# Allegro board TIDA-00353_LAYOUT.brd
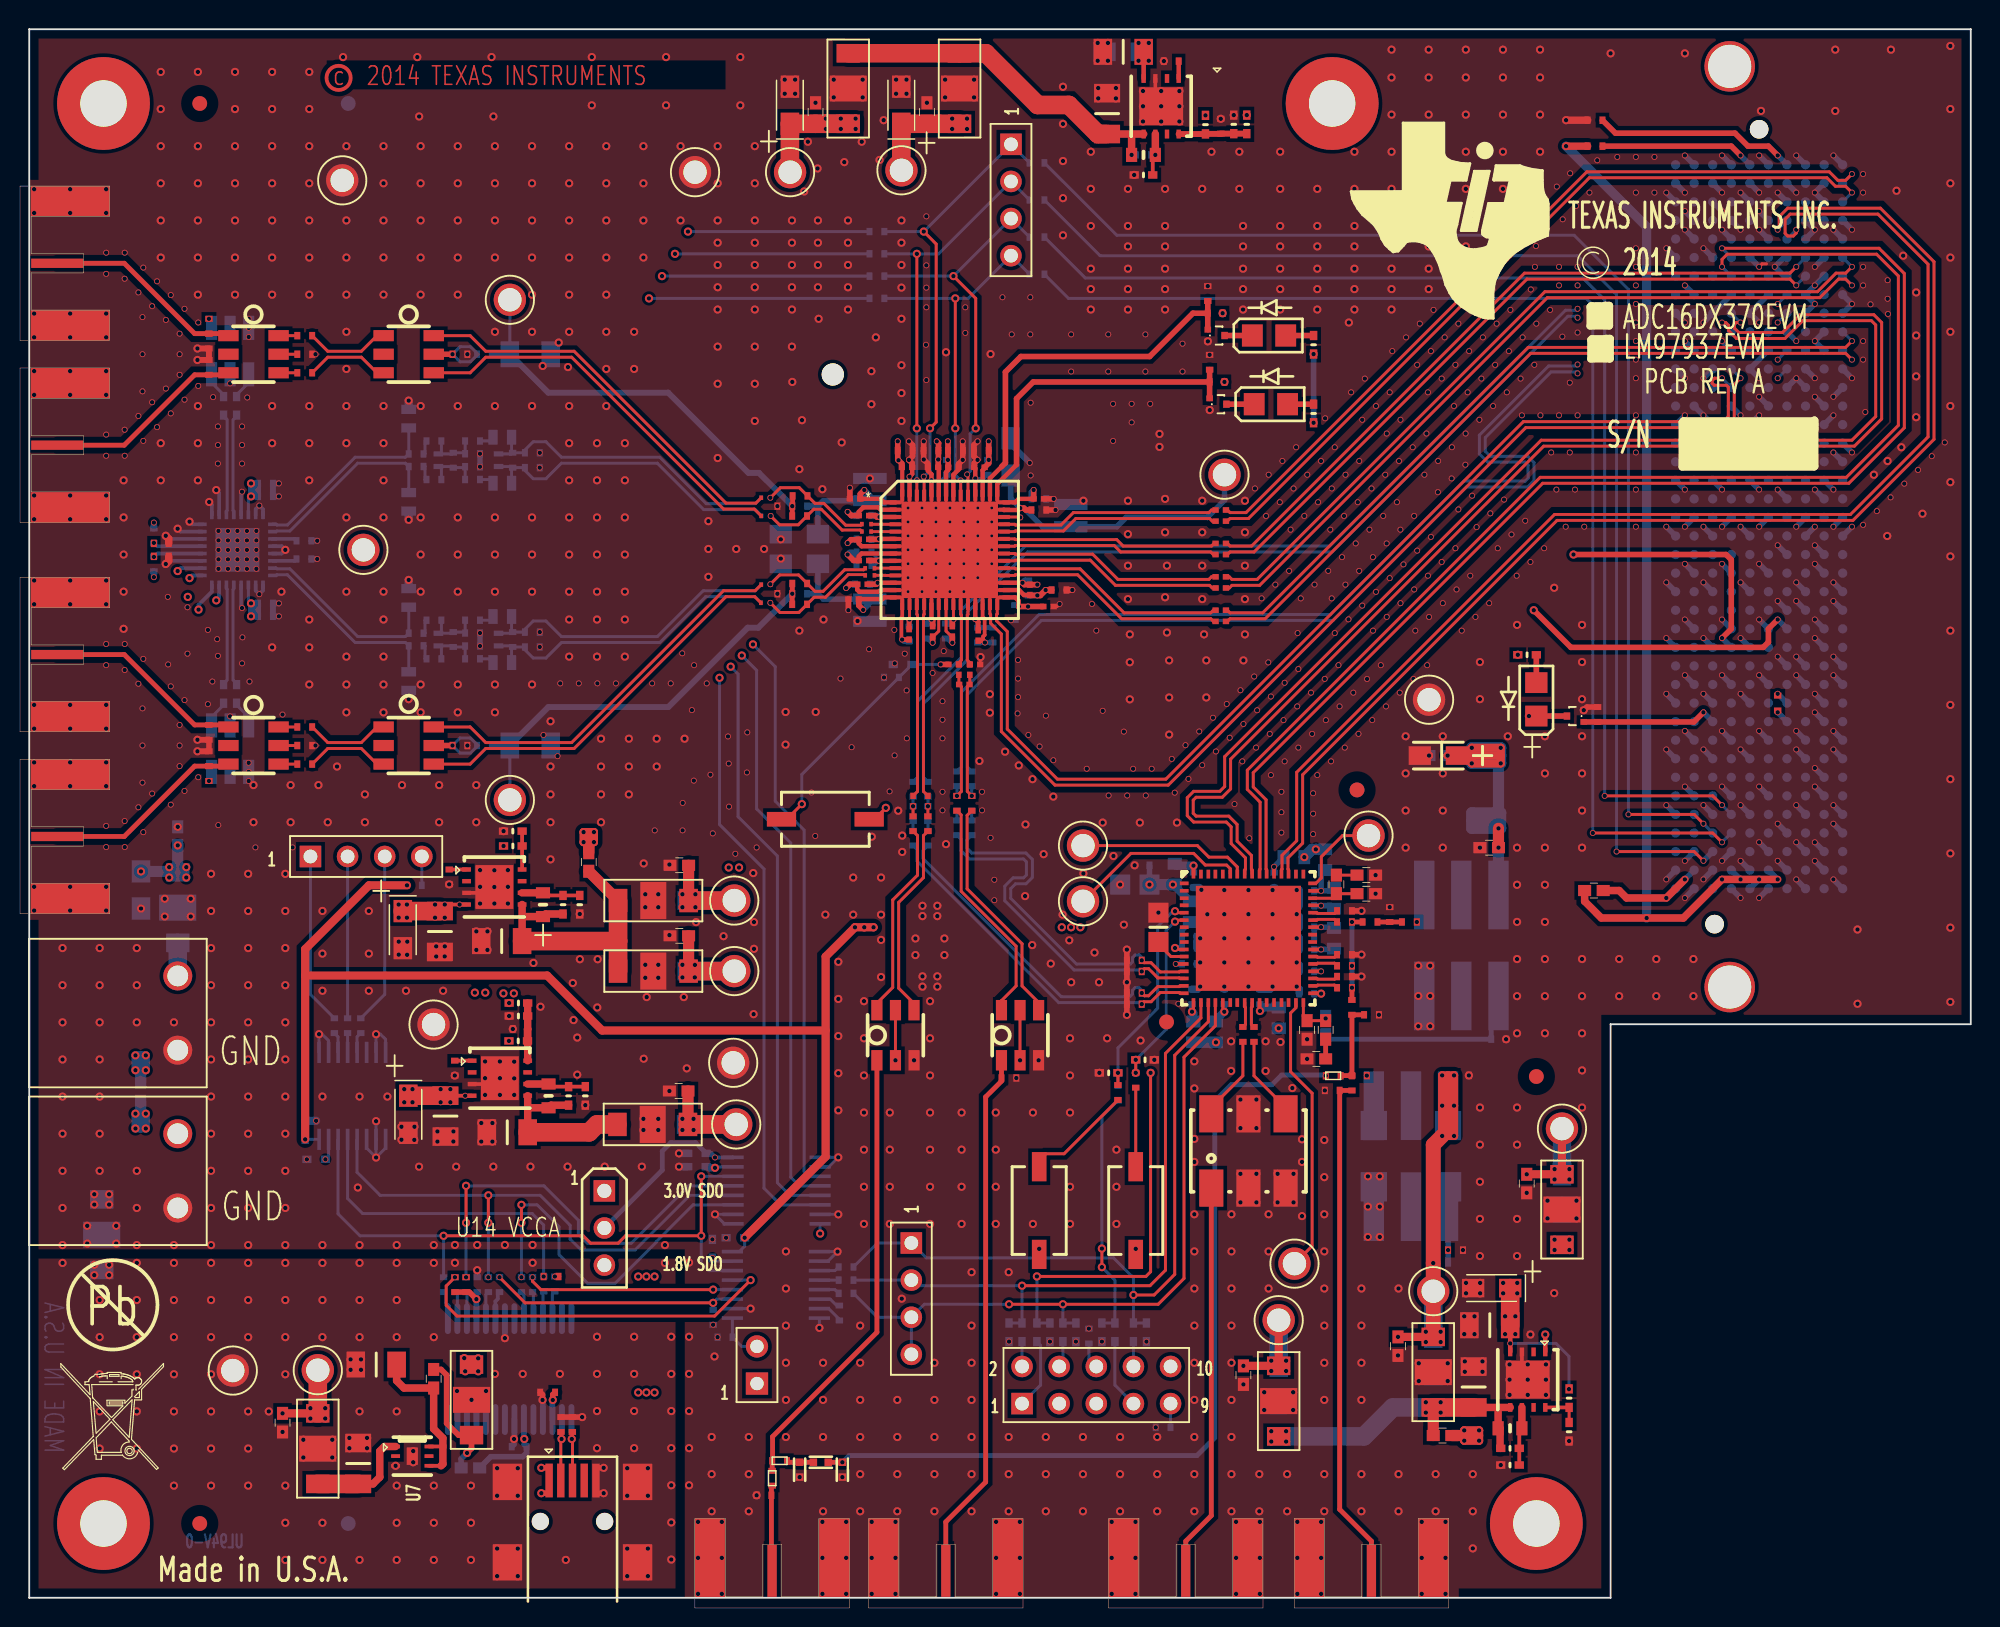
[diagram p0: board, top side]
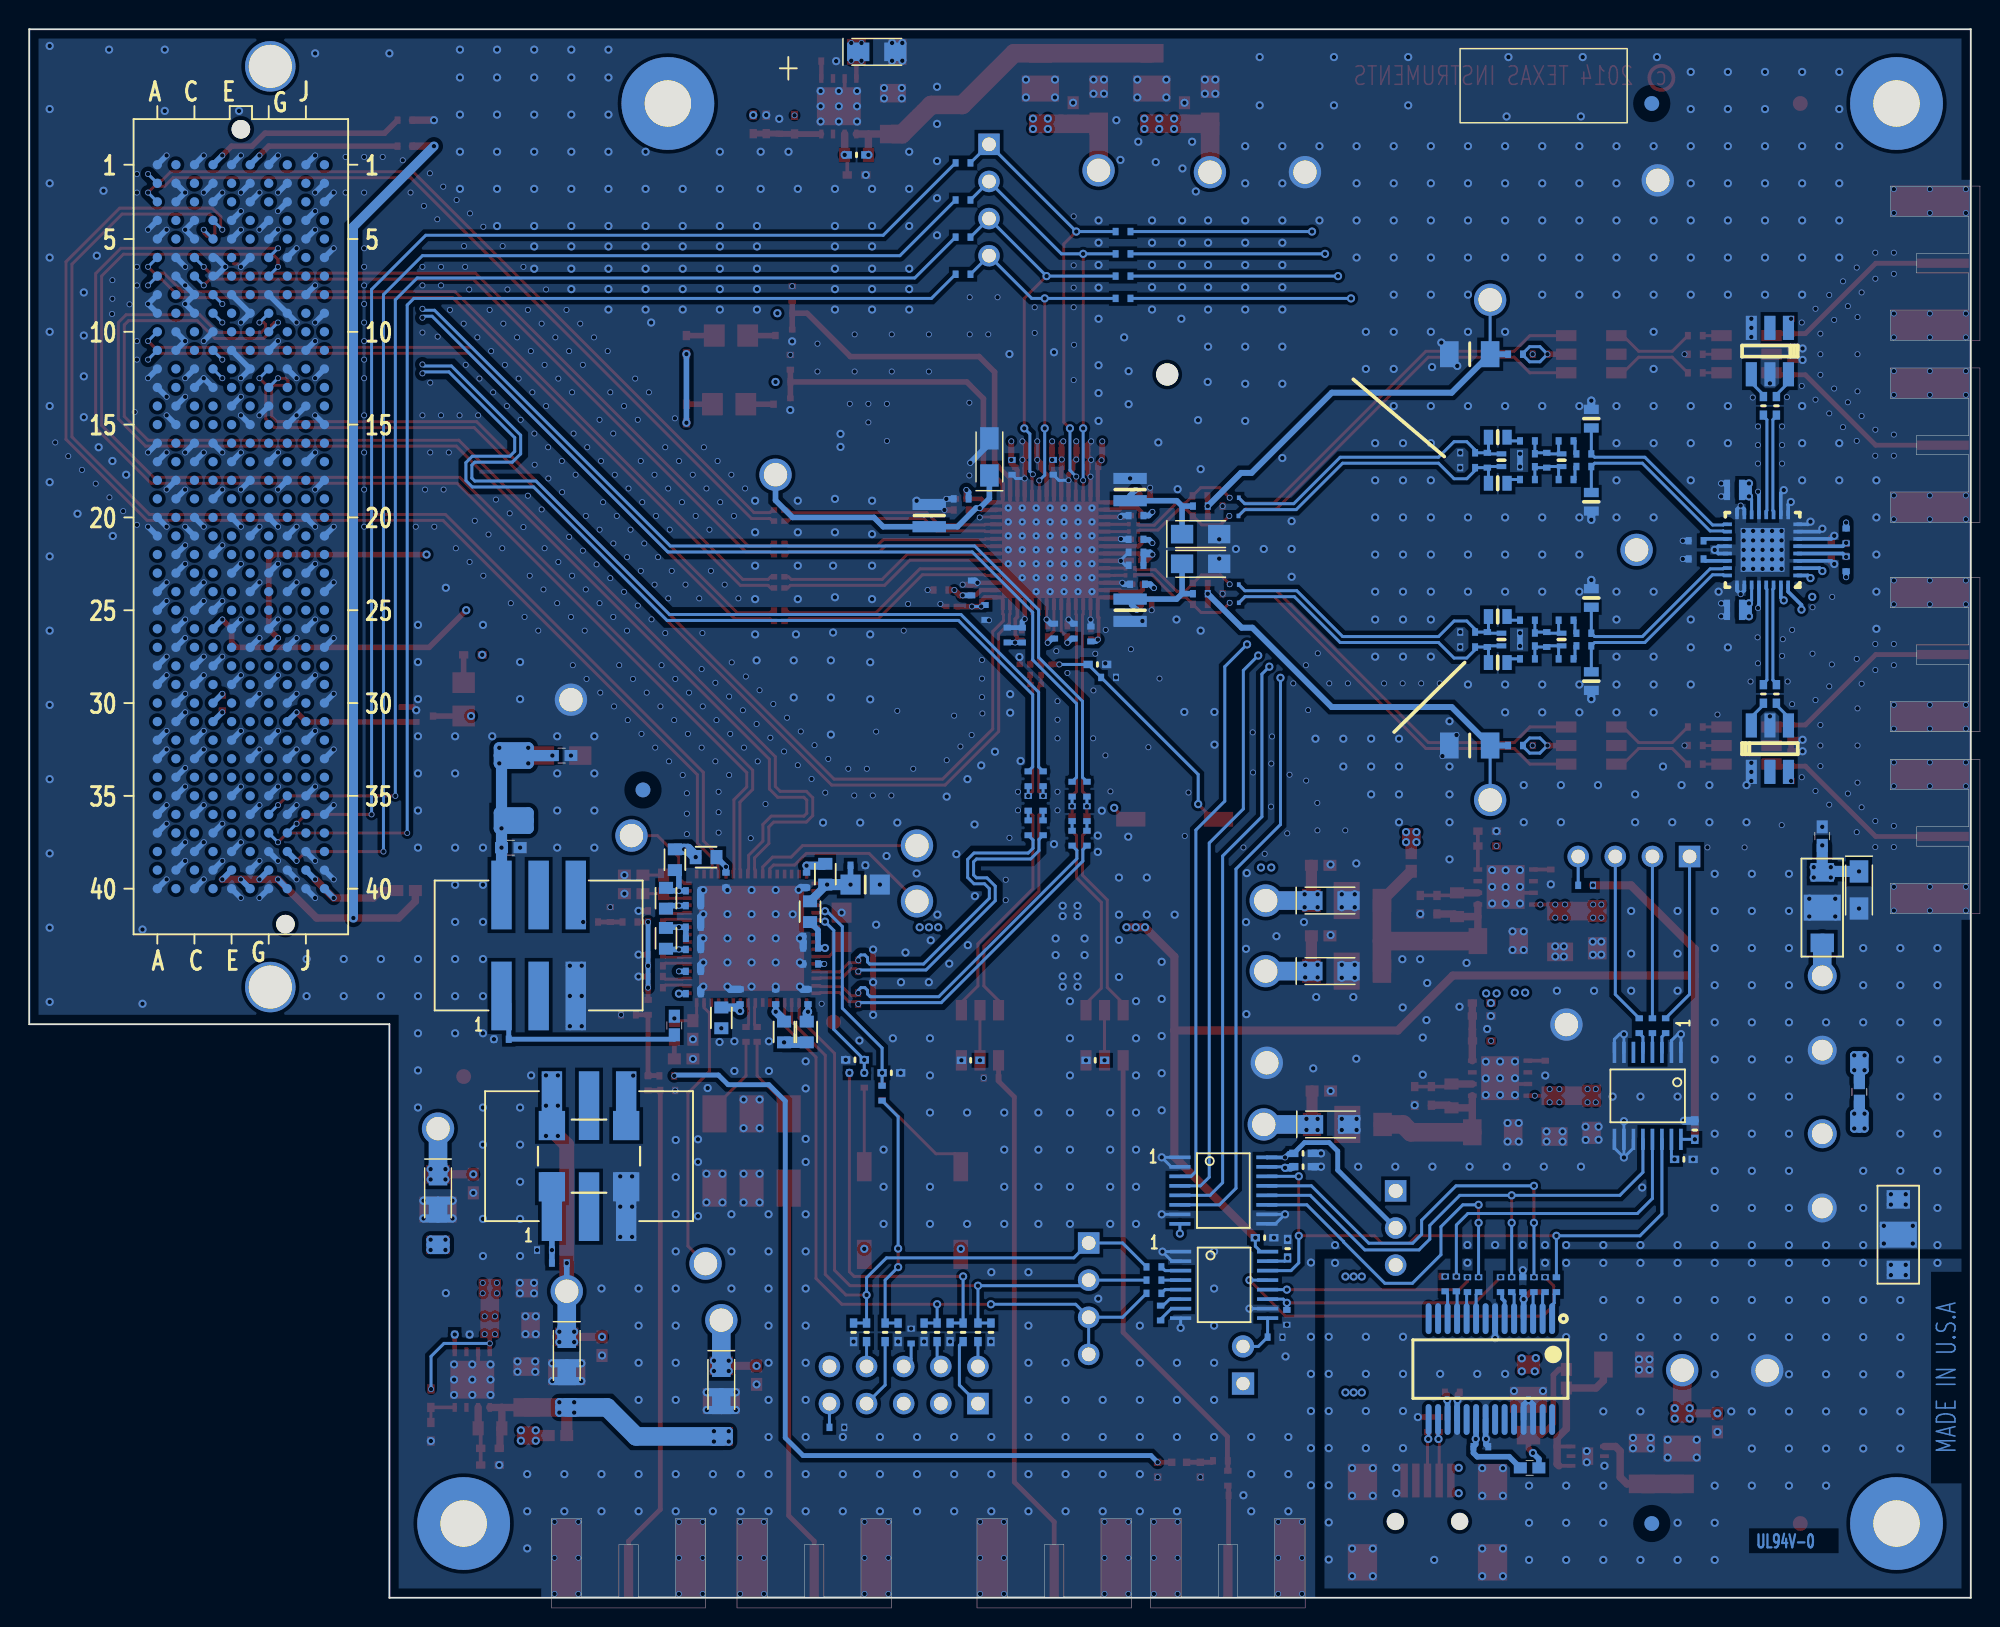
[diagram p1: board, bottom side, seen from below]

Outline 132.82 x 107.31 mm; copper layers: TOP, L2_GND, L3_POWER, L4_POWER, L5_GND, BOTTOM. Coordinates in mm from the lower left corner of the outline.
Outline path: 0,107.31 0,0 108.18,0 108.18,39.24 132.82,39.24 132.82,107.31 0,107.31

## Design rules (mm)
net group ADC_VINA: nets ADC_VINA+ ADC_VINA-
net group ADC_VINB: nets ADC_VINB+ ADC_VINB-
net group CLKIN: nets CLKIN+ CLKIN-
net group CLKOUT2: nets CLKOUT2+ CLKOUT2-
net group CLKOUT3: nets CLKOUT3+ CLKOUT3-
net group CLKOUT4: nets CLKOUT4+ CLKOUT4-
net group DIFFPAIR0: nets SA_0+ SA_0-
net group DIFFPAIR1: nets SA_1+ SA_1-
net group DIFFPAIR2: nets SB_1+ SB_1-
net group DIFFPAIR3: nets SB_0+ SB_0-
net group DIFFPAIR5: nets SYNCB+ SYNCB-
net group DP1: nets N17588912 N17591143
net group DP2: nets N17588026 N17588832
net group DP3: nets N17709160 N17709162
net group DP4: nets N17708763 N17708767
net group DP5: nets N17692293 N17692331
net group DP6: nets N17692169 N17692399
net group FMC_ADC_DEVCLK: nets FMC_ADC_DEVCLK+ FMC_ADC_DEVCLK-
net group FMC_ADC_SYSREF: nets FMC_ADC_SYSREF+ FMC_ADC_SYSREF-
net group FMC_FPGA_DEVCLKA: nets FMC_FPGA_DEVCLKA+ FMC_FPGA_DEVCLKA-
net group FMC_FPGA_DEVCLKB: nets FMC_FPGA_DEVCLKB+ FMC_FPGA_DEVCLKB-
net group FMC_FPGA_SYSREF: nets FMC_FPGA_SYSREF+ FMC_FPGA_SYSREF-
net group LMK_ADC_DEVCLK: nets LMK_ADC_DEVCLK+ LMK_ADC_DEVCLK-
net group LMK_ADC_SYSREF: nets LMK_ADC_SYSREF+ LMK_ADC_SYSREF-
net group REFCLK: nets REFCLK+ REFCLK-
net group SA0: nets SA0+ SA0-
net group SA1: nets SA1+ SA1-
net group SB0: nets SB0+ SB0-
net group SB1: nets SB1+ SB1-
net group SYSREF: nets SYSREF+ SYSREF-
net group SYSREF_VIN: nets SYSREF_VIN+ SYSREF_VIN-

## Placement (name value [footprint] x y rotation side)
BP2.5  HDR-1x1_0  [TP_500X_50]  81.77 76.83 0 top
C1  0.01u  [C0402_NO_SS]  18.85 86.35 0 top
C2  0.01u  [C0402_NO_SS]  18.85 83.81 0 top
C3  A/R  [C0402_NO_SS]  18.85 85.08 0 top
C4  0.01u  [C0402_NO_SS]  18.85 59.58 0 top
C5  0.01u  [C0402_NO_SS]  18.85 57.04 0 top
C6  A/R  [C0402_NO_SS]  18.85 58.31 0 top
C7  A/R  [C0402_NO_SS]  29.46 85.08 0 top
C8  A/R  [C0402_NO_SS]  29.46 58.31 0 top
C9  10u  [SMD_SIZE1206]  34.28 85.08 0 bottom
C10  0.1u  [C0402_NO_SS]  51.69 74.69 180 top
C11  10u  [SMD_SIZE1206]  34.28 58.31 0 bottom
C12  0.1u  [C0402_NO_SS]  51.69 68.69 180 top
C13  A/R  [C0402_NO_SS]  30.33 65.12 0 bottom
C14  A/R  [C0402_NO_SS]  30.33 66 180 bottom
C15  A/R  [C0402_NO_SS]  30.33 77.38 0 bottom
C16  A/R  [C0402_NO_SS]  30.33 78.27 180 bottom
C20  0.1u  [SMD_SIZE0402]  14.19 61.84 270 bottom
C21  0.1u  [SMD_SIZE0402]  13.3 61.84 270 bottom
C22  0.1u  [SMD_SIZE0402]  13.3 81.55 90 bottom
C23  0.1u  [SMD_SIZE0402]  14.19 81.55 90 bottom
C24  0.1u  [C0402_NO_SS]  16.16 67.15 180 bottom
C25  0.01u  [C0402_NO_SS]  16.16 68.04 0 bottom
C26  0.1u  [C0402_NO_SS]  16.16 76.24 180 bottom
C27  0.01u  [C0402_NO_SS]  16.16 75.35 0 bottom
C28  0.1u  [C0402_NO_SS]  27.69 64.24 180 bottom
C29  0.1u  [C0402_NO_SS]  27.69 66.88 180 bottom
C30  0.1u  [C0402_NO_SS]  27.69 76.51 180 bottom
C31  0.1u  [C0402_NO_SS]  27.69 79.15 180 bottom
C40  A/R  [C0402_NO_SS]  30.33 64.24 180 bottom
C41  A/R  [C0402_NO_SS]  30.33 66.88 180 bottom
C42  A/R  [C0402_NO_SS]  29.01 65.56 90 bottom
C43  A/R  [C0402_NO_SS]  33.07 65.56 90 bottom
C44  A/R  [C0402_NO_SS]  34.42 65.05 0 bottom
C45  A/R  [C0402_NO_SS]  34.42 66.07 180 bottom
C46  A/R  [C0402_NO_SS]  30.33 76.51 180 bottom
C47  A/R  [C0402_NO_SS]  30.33 79.15 180 bottom
C48  A/R  [C0402_NO_SS]  29.01 77.83 90 bottom
C49  A/R  [C0402_NO_SS]  33.07 77.83 90 bottom
C50  A/R  [C0402_NO_SS]  34.42 77.32 0 bottom
C51  A/R  [C0402_NO_SS]  34.42 78.34 180 bottom
C60  A/R  [C0402_NO_SS]  65.59 77.34 90 bottom
C61  0.1u  [C0402_NO_SS]  65.13 78.49 180 top
C62  0.01u  [0201]  65 77.34 180 top
C63  A/R  [C0402_NO_SS]  62.77 77.34 90 bottom
C64  0.1u  [C0402_NO_SS]  63.37 78.49 0 top
C65  0.01u  [0201]  63.23 77.34 0 top
C66  0.1u  [C0402_NO_SS]  59.92 78.49 0 top
C67  0.01u  [0201]  60.05 77.34 0 top
C68  0.1u  [C0402_NO_SS]  61.69 78.49 180 top
C69  0.01u  [0201]  61.83 77.34 180 top
C70  0.1u  [C0402_NO_SS]  57.1 74.04 0 bottom
C71  0.01u  [0201]  57.1 74.04 0 top
C72  0.1u  [C0402_NO_SS]  57.1 72.42 180 bottom
C73  0.01u  [0201]  57.1 72.42 180 top
C74  0.01u  [0201]  57.1 70.97 180 top
C75  0.1u  [C0402_NO_SS]  57.1 71.53 180 bottom
C76  A/R  [C0402_NO_SS]  57.1 70.64 180 bottom
C77  0.01u  [0201]  57 69.34 180 top
C78  0.1u  [C0402_NO_SS]  57 69.34 180 bottom
C79  0.1u  [C0402_NO_SS]  60.19 65.94 90 bottom
C80  0.01u  [0201]  61.8 66.12 90 top
C81  0.1u  [C0402_NO_SS]  61.35 66.14 90 bottom
C82  0.01u  [0201]  60.19 65.91 90 top
C84  0.1u  [C0402_NO_SS]  62.69 66.14 90 bottom
C85  0.01u  [0201]  63.15 66.12 90 top
C86  A/R  [C0402_NO_SS]  65.91 65.87 270 bottom
C87  0.1u  [C0402_NO_SS]  64.89 65.86 90 bottom
C88  0.01u  [0201]  64.92 65.84 90 top
C89  0.1u  [C0402_NO_SS]  67.44 67.41 90 bottom
C90  0.01u  [0201]  69.73 67.82 180 top
C91  A/R  [C0402_NO_SS]  68.36 69.09 90 bottom
C92  0.1u  [C0402_NO_SS]  70.45 68.95 0 top
C93  0.01u  [0201]  68.46 68.96 90 top
C94  0.01u  [0201]  69.07 75.18 180 top
C95  0.1u  [C0402_NO_SS]  69.07 75.18 180 bottom
C96  0.1u  [C0402_NO_SS]  69.07 74.42 0 top
C97  1u  [0508]  71.25 74.04 270 bottom
C98  10uF  [CAP_A-CASE]  67.14 78.06 90 bottom
C100  0.01u  [0201]  81.51 74.42 180 top
C101  0.01u  [0201]  81.51 73.66 180 top
C102  0.01u  [0201]  81.51 72.14 180 top
C103  0.01u  [0201]  81.51 71.37 180 top
C104  0.01u  [0201]  81.51 69.85 180 top
C105  0.01u  [0201]  81.51 69.09 180 top
C106  0.01u  [0201]  81.51 67.56 180 top
C107  0.01u  [0201]  81.51 66.8 180 top
C108  0.1u  [0201]  60.46 54.51 90 top
C109  0.1u  [0201]  61.48 54.51 90 top
C110  0.1u  [0201]  63.6 63.5 90 top
C111  0.1u  [0201]  64.35 63.5 90 top
C112  A/R  [0201]  64.7 63.86 0 top
C113  0.1u  [SMD_SIZE0402]  59.75 63.86 0 bottom
C114  0.1u  [0201]  56.49 75.18 180 top
C115  1u  [0508]  57.51 75.82 90 bottom
C116  10uF  [CAP_A-CASE]  52.68 72.77 180 bottom
C117  0.1u  [0201]  56.39 68.33 180 top
C118  1u  [0508]  57.51 67.56 270 bottom
C119  10uF  [CAP_A-CASE]  52.68 70.74 180 bottom
C120  A/R  [SMD_SIZE0402]  59.89 36.77 180 bottom
C121  A/R  [SMD_SIZE0402]  68.42 36.77 180 bottom
C130  1u  [C0402_NO_SS]  79.37 45.24 0 bottom
C131  0.1u  [C0402_NO_SS]  79.37 44.46 0 bottom
C132  0.1u  [C0402_NO_SS]  87.39 41.33 180 bottom
C133  0.1u  [C0402_NO_SS]  87.39 42.86 180 bottom
C134  10u  [0805]  75.63 48.79 180 bottom
C135  1u  [C0402_NO_SS]  76.13 50.11 180 bottom
C136  0.1u  [C0402_NO_SS]  87.39 44.36 180 bottom
C137  0.1u  [C0402_NO_SS]  87.39 47.35 180 bottom
C138  1u  [C0402_NO_SS]  87.39 45.12 180 bottom
C139  0.1u  [C0402_NO_SS]  87.39 48.37 180 bottom
C140  0.1u  [C0402_NO_SS]  87.39 45.88 180 bottom
C141  0.1u  [C0402_NO_SS]  79.55 41.12 90 bottom
C142  0.1u  [C0402_NO_SS]  81.75 41.12 90 bottom
C143  0.1u  [C0402_NO_SS]  84.19 41.12 90 bottom
C144  0.1u  [C0402_NO_SS]  85.16 49.1 270 bottom
C145  0.1u  [C0402_NO_SS]  79.65 49.1 270 bottom
C146  0.1u  [SMD_SIZE0402]  73.84 35.92 0 top
C147  0.1u  [SMD_SIZE0402]  76.33 36.8 180 bottom
C148  10u  [0805]  77.25 45.87 90 top
C149  0.1u  [C0402_NO_SS]  79.37 43.36 0 bottom
C150  .022uF  [0603]  89.43 48.81 90 top
C151  390p  [0603]  91.47 48.17 0 top
C152  0.1u  [C0402_NO_SS]  89.98 47 0 top
C153  A/R  [C0402_NO_SS]  89.98 46.23 0 top
C154  0.1u  [C0402_NO_SS]  89.98 44 0 top
C155  A/R  [C0402_NO_SS]  89.98 43.24 0 top
C156  0.1u  [C0402_NO_SS]  89.98 42.5 0 top
C157  0.1u  [C0402_NO_SS]  89.98 41.74 0 top
C158  A/R  [C0402_NO_SS]  91.72 46.23 0 top
C159  0.1u  [C0402_NO_SS]  90.49 40.39 90 top
C160  8200p  [0603]  87.42 38.85 270 top
C161  0.39u  [0603]  88.69 38.85 270 top
C162  A/R  [C0402_NO_SS]  100.53 38.21 0 bottom
C163  100p  [0603]  99.88 51.32 180 bottom
C164  0.1u  [0603]  99.88 51.32 180 top
C165  0.1u  [C0402_NO_SS]  83.79 38.54 270 top
C166  0.1u  [C0402_NO_SS]  83.02 38.54 270 top
C167  A/R  [C0402_NO_SS]  97.98 35.74 0 top
C168  A/R  [C0402_NO_SS]  97.57 23.79 0 bottom
C169  10u  [SMD_SIZE3216]  96.4 57.62 180 top
C170  0.1u  [C0402_NO_SS]  63.46 52.68 90 bottom
C171  0.1u  [C0402_NO_SS]  64.48 52.68 90 bottom
C172  0.1u  [C0402_NO_SS]  60.46 51.97 90 bottom
C173  0.1u  [C0402_NO_SS]  61.48 51.97 90 bottom
C174  0.1u  [0603]  96.4 57.62 180 bottom
C180  10u  [SMD_SIZE1206]  23.74 15.95 180 top
C181  10u  [SMD_SIZE1206]  22.5 9.19 90 top
C182  0.1u  [0603]  17.33 11.98 270 top
C183  0.01u  [C0402_NO_SS]  33.52 10.34 180 bottom
C184  0.01u  [C0402_NO_SS]  30.65 21.42 90 bottom
C185  47p  [C0402_NO_SS]  36.38 11.85 90 top
C186  47p  [C0402_NO_SS]  37.15 11.85 90 top
C187  0.1u  [C0402_NO_SS]  35.47 14.05 180 top
C190  0.1u  [SMD_SIZE0402]  45.68 29.49 0 bottom
C191  0.1u  [SMD_SIZE0402]  18.88 32 270 bottom
C192  0.1u  [SMD_SIZE0402]  19.63 30 0 bottom
C193  0.1u  [SMD_SIZE0402]  48.31 24.63 0 bottom
C194  0.1u  [SMD_SIZE0402]  46.74 23.88 270 bottom
C195  0.1u  [SMD_SIZE0402]  45.68 30.4 0 bottom
C200  0.1u  [C0402_NO_SS]  81.51 100.68 270 top
C201  10uF  [CAP_A-CASE]  74.84 105.77 180 bottom
C202  1u  [SMD_SIZE1206]  74.84 105.77 180 top
C203  0.01u  [C0402_NO_SS]  78.13 105.13 180 top
C204  10u  [SMD_SIZE1206]  73.74 101.54 90 top
C205  2.2n  [SMD_SIZE0603]  76.23 98.72 0 top
C206  10uF  [CAP_A-CASE]  52.04 102.12 90 top
C207  0.1u  [0603]  53.79 101.65 90 top
C208  10uF  [CAP_A-CASE]  59.66 102.12 90 top
C209  0.1u  [0603]  61.41 101.65 90 top
C210  1uF  [C0402_NO_SS]  33.59 38.91 0 top
C211  10uF  [CAP_A-CASE]  25.94 33.08 270 top
C212  1u  [SMD_SIZE1206]  28.48 32.95 270 top
C213  0.01u  [C0402_NO_SS]  29.11 36.24 270 top
C214  10u  [SMD_SIZE1206]  32.7 31.85 180 top
C215  2.2n  [SMD_SIZE0603]  35.53 34.34 90 top
C216  10uF  [CAP_A-CASE]  43.79 32.38 180 bottom
C217  0.1u  [0603]  44.43 34.67 180 top
C220  10uF  [CAP_A-CASE]  25.55 45.71 270 top
C221  1u  [SMD_SIZE1206]  28.09 45.58 270 top
C222  0.01u  [C0402_NO_SS]  28.73 49.32 270 top
C223  10u  [SMD_SIZE1206]  32.32 44.93 180 top
C224  2.2n  [SMD_SIZE0603]  35.15 47.42 90 top
C225  10uF  [CAP_A-CASE]  43.84 42.88 180 bottom
C226  0.1u  [0603]  44.47 45.29 180 top
C227  10uF  [CAP_A-CASE]  43.84 47.7 180 bottom
C228  0.1u  [0603]  44.47 50.11 180 top
C230  10uF  [CAP_A-CASE]  100.04 21.19 180 top
C231  1u  [SMD_SIZE1206]  99.92 18.65 180 top
C232  0.01u  [C0402_NO_SS]  103.2 18.01 180 bottom
C233  2.2n  [SMD_SIZE0603]  101.3 11.6 0 top
C234  10u  [SMD_SIZE1206]  98.81 14.42 90 top
C235  10uF  [CAP_A-CASE]  85.48 14.6 270 bottom
C236  0.1u  [0603]  83.06 15.23 270 top
C237  10uF  [CAP_A-CASE]  96.05 16.58 270 bottom
C238  0.1u  [0603]  93.64 17.21 270 top
C239  10uF  [CAP_A-CASE]  104.86 27.7 270 bottom
C240  0.1u  [0603]  102.44 28.34 270 top
C241  10uF  [CAP_A-CASE]  7.65 48.43 270 bottom
C242  0.1u  [0603]  10.16 52.11 90 bottom
CLK  CLK_DIFF  [CON_SMA-EDGE]  50.82 1.84 90 top
CLKIN_SEL0  HDR-1x1_0  [TP_500X_50]  72.09 51.46 0 top
CLKIN_SEL1  HDR-1x1_0  [TP_500X_50]  72.09 47.65 0 top
EXTREF  CLK_DIFF  [CON_SMA-EDGE]  91.82 1.84 90 top
FMC  ASP-134488-01_0  [CONN_SEAM_040]  118.34 73.28 270 bottom
GND  TP, BLACK  [TP_500X_50]  21.41 96.98 0 top
GND1  TP, BLACK  [TP_500X_50]  95.76 61.44 0 top
GND1.2  TP, BLACK  [TP_500X_50]  45.55 97.54 0 top
GND1.8  TP, BLACK  [TP_500X_50]  48.16 36.6 0 top
GND2  TP, BLACK  [TP_500X_50]  13.92 15.54 0 top
GND3.0  TP, BLACK  [TP_500X_50]  27.66 39.22 0 top
J1  HDR-1x4  [BLKCON_4X1]  23.05 50.72 90 top
J2  HDR-1x4  [BLKCON_4X1]  60.35 20.46 0 top
J3  HDR-1x4  [BLKCON_4X1]  67.16 95.63 0 top
JP1  Jumper_1x3_100_430L  [HDR_THVT_1X3_100_M]  39.34 27.84 0 top
JP2  HDR-1x2  [BLKCON_2X1]  49.79 15.93 180 top
L1  1u  [COILCRAFT_SIZE0603LS]  25.96 62.72 270 bottom
L2  1u  [COILCRAFT_SIZE0603LS]  25.96 68.4 90 bottom
L3  1u  [COILCRAFT_SIZE0603LS]  25.96 80.67 270 bottom
L4  1u  [COILCRAFT_SIZE0603LS]  25.96 74.98 90 bottom
L5  A/R  [COILCRAFT_SIZE0402HP]  27.99 65.56 270 bottom
L6  A/R  [COILCRAFT_SIZE0603CS]  32.36 63.99 0 bottom
L7  A/R  [COILCRAFT_SIZE0603CS]  32.36 67.13 0 bottom
L8  A/R  [COILCRAFT_SIZE0402HP]  32.11 65.56 270 bottom
L9  A/R  [COILCRAFT_SIZE0402HP]  27.99 77.83 270 bottom
L10  A/R  [COILCRAFT_SIZE0603CS]  32.36 76.25 0 bottom
L11  A/R  [COILCRAFT_SIZE0603CS]  32.36 79.4 0 bottom
L12  A/R  [COILCRAFT_SIZE0402HP]  32.11 77.83 270 bottom
L20  INDUCTOR FERRITE/SM  [R0603]  79.41 46.94 90 bottom
L21  INDUCTOR FERRITE/SM  [R0603]  88.65 50.5 90 bottom
L22  INDUCTOR FERRITE/SM  [R0603]  89.26 45.12 270 bottom
L23  INDUCTOR FERRITE/SM  [R0603]  89.26 47.86 270 bottom
L24  INDUCTOR FERRITE/SM  [R0603]  79.63 38.71 90 bottom
L25  INDUCTOR FERRITE/SM  [R0603]  81.18 38.71 90 bottom
L26  INDUCTOR FERRITE/SM  [R0603]  85.48 39.67 90 bottom
L27  INDUCTOR FERRITE/SM  [R0603]  86.52 50.67 180 bottom
L28  INDUCTOR FERRITE/SM  [R0603]  78.36 49.5 90 bottom
LMK_RESET  PUSH_BUTTON  [EVQPPD]  69.09 26.49 90 top
LMK_SYNC  PUSH_BUTTON  [EVQPPD]  75.7 26.49 90 top
LMKSPI  HDR2x5  [BLKCON_5X2]  73 14.55 90 top
MT1  TP  [VIA85D55]  5.08 5.08 0 top
MT2  TP  [VIA85D55]  103.1 5.08 0 top
MT3  TP  [VIA85D55]  5.08 102.23 0 top
MT4  TP  [VIA85D55]  89.13 102.23 0 top
MT5  TP  [VIA85D55]  116.33 41.78 0 top
MT6  TP  [VIA85D55]  116.33 104.78 0 top
NOREF  -  []  272.03 -42.11 0 top
NOREF#2  -  []  -75.67 -203.28 0 top
NOREF#3  -  []  3.68 18.77 0 top
NOREF#4  -  [unnamed#2]  90.84 55.27 0 top
NOREF#5  -  [unnamed#2]  103.1 35.66 0 top
NOREF#6  -  []  5.61 12.55 0 top
NOREF#7  -  []  0 107.31 0 top
NOREF#8  -  []  98.48 94.77 0 top
NOREF#9  -  [unnamed#2]  11.66 102.23 0 top
NOREF#10  -  []  9.63 -4.32 0 top
NOREF#11  -  []  0 0 0 top
NOREF#12  -  []  125.22 51.74 0 top
NOREF#13  -  [unnamed#2]  77.81 39.4 0 top
NOREF#14  -  []  162.29 109.6 0 top
NOREF#15  -  []  8.64 1.19 0 top
NOREF#16  -  [unnamed#2]  11.66 5.08 0 top
NOREF#17  -  []  0 0 90 top
NOREF#18  -  []  108.18 0 90 top
NOREF#19  -  [unnamed#2]  21.82 102.23 180 bottom
NOREF#20  -  [unnamed#2]  21.82 5.08 180 bottom
NOREF#21  -  [unnamed#2]  90.84 55.27 180 bottom
OVRA/TRIGRDY  LED  [LED_0805]  84.82 86.36 180 top
OVRB/TRIGGER  LED  [LED_0805]  84.94 81.66 180 top
Q2  SSM3K37MFV,L3F  [SOT-723]  81.2 86.36 270 top
Q3  SSM3K37MFV,L3F  [SOT-723]  81.33 81.66 270 top
Q4  SSM3K37MFV,L3F  [SOT-723]  105.77 60.33 90 top
R1  0  [C0402_NO_SS]  12.29 85.98 90 top
R2  A/R  [C0402_NO_SS]  12.29 84.18 90 top
R3  A/R  [C0402_NO_SS]  12.29 87 90 top
R4  0  [C0402_NO_SS]  12.29 59.21 90 top
R5  A/R  [C0402_NO_SS]  12.29 57.41 270 top
R6  A/R  [C0402_NO_SS]  12.29 56.39 90 top
R7  A/R  [C0402_NO_SS]  31.14 85.08 0 bottom
R8  0  [C0201_NO_SS]  50.39 75.26 180 top
R9  0  [C0201_NO_SS]  50.39 74.02 180 top
R10  33, 1%  [C0402_NO_SS]  52.73 75.39 180 top
R11  33, 1%  [C0402_NO_SS]  52.7 74.01 180 top
R12  0  [C0201_NO_SS]  57.28 73.46 180 top
R13  0  [C0201_NO_SS]  57.28 72.95 180 top
R14  A/R  [C0201_NO_SS]  50.39 75.26 180 bottom
R15  A/R  [C0201_NO_SS]  50.42 74.02 180 bottom
R16  10  [C0402_NO_SS]  52.7 74.69 0 bottom
R17  499  [C0402_NO_SS]  26.35 48.74 0 bottom
R20  0  [C0201_NO_SS]  50.39 69.32 180 top
R21  0  [C0201_NO_SS]  50.37 68.07 180 top
R22  33, 1%  [C0402_NO_SS]  52.71 69.4 180 top
R23  33, 1%  [C0402_NO_SS]  52.7 67.97 180 top
R24  0  [C0201_NO_SS]  57.51 70.43 180 top
R25  0  [C0201_NO_SS]  57.51 69.95 180 top
R26  A/R  [C0402_NO_SS]  31.14 58.31 0 bottom
R27  10  [C0402_NO_SS]  52.7 68.7 0 bottom
R28  A/R  [C0201_NO_SS]  50.39 69.32 0 bottom
R29  A/R  [C0201_NO_SS]  50.39 68.07 0 bottom
R30  A/R  [C0402_NO_SS]  8.53 70.74 270 bottom
R31  0  [C0402_NO_SS]  9.03 71.25 0 top
R32  24k  [C0402_NO_SS]  9.03 72.14 0 top
R33  10K  [C0402_NO_SS]  8.53 72.65 90 bottom
R34  A/R  [C0402_NO_SS]  18.79 71.07 180 bottom
R35  A/R  [C0402_NO_SS]  18.79 72.32 180 bottom
R36  39, 1%  [C0402_NO_SS]  26.47 65.13 180 bottom
R37  39, 1%  [C0402_NO_SS]  26.47 65.99 180 bottom
R38  39, 1%  [C0402_NO_SS]  26.47 77.4 180 bottom
R39  39, 1%  [C0402_NO_SS]  26.47 78.26 180 bottom
R40  0  [C0402_NO_SS]  77.57 11.66 0 bottom
R50  100  [0201]  63.97 62.48 180 top
R51  A/R  [0201]  63.24 63.86 180 top
R52  10K  [C0402_NO_SS]  58.98 62.97 180 bottom
R53  22  [C0402_NO_SS]  81.13 87.88 0 top
R54  22  [C0402_NO_SS]  81.26 83.19 0 top
R55  10K  [C0402_NO_SS]  80.75 84.53 270 top
R56  10K  [C0402_NO_SS]  80.62 89.23 270 top
R57  56  [SMD_SIZE0402]  87.86 81.03 270 top
R58  56  [SMD_SIZE0402]  87.86 85.72 270 top
R60  10K  [C0402_NO_SS]  107.12 101.09 180 top
R61  10K  [C0402_NO_SS]  107.12 99.31 180 top
R62  0  [C0402_NO_SS]  119.61 61.21 90 top
R63  A/R  [C0402_NO_SS]  68.94 93.09 0 bottom
R64  A/R  [C0402_NO_SS]  68.94 90.55 0 bottom
R65  A/R  [C0402_NO_SS]  68.94 98.17 180 bottom
R66  A/R  [C0402_NO_SS]  68.94 95.63 180 bottom
R67  10K  [C0402_NO_SS]  107.29 60.43 90 top
R68  56  [SMD_SIZE0402]  102.47 64.52 0 top
R69  0  [0603]  107.04 48.39 0 top
R70  100  [C0402_NO_SS]  50.27 7.01 180 top
R71  100  [C0402_NO_SS]  67.02 35.56 0 top
R72  0  [C0402_NO_SS]  60.46 52.96 90 top
R73  0  [C0402_NO_SS]  61.48 52.96 90 top
R74  A/R  [C0402_NO_SS]  60.46 53.64 90 bottom
R75  A/R  [C0402_NO_SS]  61.48 53.64 90 bottom
R76  A/R  [C0402_NO_SS]  60.46 55.32 270 bottom
R77  A/R  [C0402_NO_SS]  61.48 55.32 270 bottom
R78  0  [C0402_NO_SS]  63.46 54.36 90 top
R79  0  [C0402_NO_SS]  64.48 54.36 90 top
R80  A/R  [C0402_NO_SS]  64.48 54.36 90 bottom
R81  A/R  [C0402_NO_SS]  63.46 54.36 90 bottom
R82  A/R  [C0402_NO_SS]  64.48 56.03 270 bottom
R83  A/R  [C0402_NO_SS]  63.46 56.03 270 bottom
R90  121  [C0402_NO_SS]  75.6 42.85 0 top
R91  121  [C0402_NO_SS]  75.6 43.61 0 top
R92  121  [C0402_NO_SS]  75.6 40.62 0 top
R93  121  [C0402_NO_SS]  75.6 41.38 0 top
R94  0  [C0402_NO_SS]  74.48 34.57 90 top
R95  A/R  [C0402_NO_SS]  74.48 34.52 90 bottom
R96  A/R  [C0402_NO_SS]  76.21 35.92 180 bottom
R97  0  [C0402_NO_SS]  75.7 35.41 90 top
R98  1K  [SMD_SIZE0402]  73.84 35.92 180 bottom
R99  1K  [SMD_SIZE0402]  76.33 36.8 0 top
R100  470  [0603]  91.47 49.44 0 top
R101  A/R  [C0402_NO_SS]  93.07 46.74 270 top
R102  A/R  [C0402_NO_SS]  94.42 46.23 0 top
R103  0  [0603]  88.69 39.15 270 bottom
R104  3.30k  [0603]  88.05 36.87 180 top
R107  49.9  [C0402_NO_SS]  89.14 34.71 0 top
R108  200  [C0402_NO_SS]  90.49 35.22 90 top
R109  200  [C0402_NO_SS]  91.83 39.88 180 top
R110  A/R  [C0402_NO_SS]  90.99 35.73 0 top
R111  A/R  [C0402_NO_SS]  97.57 23.79 180 top
R112  A/R  [C0402_NO_SS]  96.56 22.9 180 bottom
R119  0  [0603]  30.18 8.89 0 bottom
R120  0  [0603]  27.67 14.99 90 top
R121  10K  [C0402_NO_SS]  35.96 21.47 90 bottom
R122  10K  [C0402_NO_SS]  29.88 21.42 270 top
R123  10K  [C0402_NO_SS]  35.7 21.98 0 top
R124  10K  [C0402_NO_SS]  29.12 21.42 270 top
R125  10K  [C0402_NO_SS]  46.79 19.19 90 bottom
R126  22  [C0402_NO_SS]  28.35 21.42 90 bottom
R127  22  [C0402_NO_SS]  31.41 21.42 90 bottom
R128  22  [C0402_NO_SS]  29.88 21.42 90 bottom
R129  22  [C0402_NO_SS]  35.19 21.47 90 bottom
R130  22  [C0402_NO_SS]  29.12 21.42 90 bottom
R131  22  [C0402_NO_SS]  33.67 21.42 90 bottom
R132  22  [C0402_NO_SS]  34.43 21.42 90 bottom
R133  22  [C0402_NO_SS]  32.17 21.42 90 bottom
R134  22  [C0402_NO_SS]  57.99 93.47 0 bottom
R135  22  [C0402_NO_SS]  57.99 91.95 0 bottom
R136  22  [C0402_NO_SS]  57.99 90.42 0 bottom
R137  22  [C0402_NO_SS]  57.99 88.9 0 bottom
R138  22  [C0402_NO_SS]  20.87 39.14 90 bottom
R139  22  [C0402_NO_SS]  21.78 39.14 90 bottom
R140  22  [C0402_NO_SS]  22.68 39.14 90 bottom
R141  22  [C0402_NO_SS]  55.88 22.64 0 bottom
R142  22  [C0402_NO_SS]  55.88 21.73 0 bottom
R143  22  [C0402_NO_SS]  55.88 20.83 0 bottom
R144  22  [C0402_NO_SS]  55.42 19.48 270 bottom
R145  0  [C0402_NO_SS]  72.49 17.91 90 bottom
R146  24k  [SMD_SIZE0402]  67.03 18.16 270 bottom
R147  15k  [SMD_SIZE0402]  67.92 18.16 270 bottom
R148  24k  [SMD_SIZE0402]  71.6 18.16 270 bottom
R149  15k  [SMD_SIZE0402]  70.71 18.16 270 bottom
R150  24k  [SMD_SIZE0402]  76.43 18.16 270 bottom
R151  15k  [SMD_SIZE0402]  75.54 18.16 270 bottom
R152  15k  [SMD_SIZE0402]  74.27 18.16 90 bottom
R153  24k  [SMD_SIZE0402]  73.38 18.16 270 bottom
R155  24k  [SMD_SIZE0402]  69.82 18.16 270 bottom
R156  15k  [SMD_SIZE0402]  68.94 18.16 90 bottom
R159  10K  [C0402_NO_SS]  47.6 17.83 180 bottom
R160  1k  [SMD_SIZE0402]  83.29 100.8 270 top
R161  A/R  [SMD_SIZE0402]  82.4 100.8 270 top
R162  200  [SMD_SIZE0402]  76.23 98.72 180 bottom
R163  1k  [SMD_SIZE0402]  76.23 97.35 180 top
R164  10K  [SMD_SIZE0402]  33.46 40.69 0 top
R165  A/R  [SMD_SIZE0402]  33.46 39.8 0 top
R166  806  [SMD_SIZE0402]  36.9 34.34 270 top
R167  1k  [SMD_SIZE0402]  38.04 34.34 270 top
R168  1k  [SMD_SIZE0402]  33.08 51.44 0 top
R169  A/R  [SMD_SIZE0402]  33.08 52.45 180 top
R170  2.10K  [SMD_SIZE0402]  36.52 47.42 270 top
R171  1k  [SMD_SIZE0402]  37.66 47.42 270 top
R175  1k  [SMD_SIZE0402]  105.35 13.66 270 top
R176  A/R  [SMD_SIZE0402]  105.35 11.36 270 top
R177  2.32K  [SMD_SIZE0402]  101.3 10.22 180 top
R178  1k  [SMD_SIZE0402]  101.3 9.08 180 top
R179  A/R  [0603]  38.28 50.34 90 top
R180  A/R  [0603]  96.68 11.1 0 top
R181  A/R  [0603]  7.62 34.61 90 bottom
R217  300  [0402]  52.7 8.89 90 top
R218  300  [0402]  55.63 8.89 90 top
R219  75  [0402]  54.03 9.27 180 top
R220  0  [C0402_NO_SS]  50.83 8.18 90 top
R221  0  [C0402_NO_SS]  51.33 9.37 0 top
R234  0  [C0402_NO_SS]  89.2 35.71 180 top
R235  A/R  [SMD_SIZE0402]  80.47 100.79 270 top
R236  A/R  [SMD_SIZE0402]  33.45 38.1 0 top
REFCLK  CLK_DIFF  [CON_SMA-EDGE]  79.12 1.84 90 top
STATUS_LD1  HDR-1x1_0  [TP_500X_50]  86.56 22.86 0 top
STATUS_LD2  HDR-1x1_0  [TP_500X_50]  91.62 52.15 0 top
SYNC  LED  [LED_0805]  103.1 61.47 270 top
SYSREF  CLK_DIFF  [CON_SMA-EDGE]  62.7 1.84 90 top
SYSREF_SW  PUSH_BUTTON  [EVQPPD]  54.46 53.26 180 top
T1  -  [MABA-007159-000000]  15.34 85.08 270 top
T2  -  [MABA-007159-000000]  25.96 85.08 270 top
T3  -  [MABA-007159-000000]  59.26 38.49 0 top
T4  -  [MABA-007159-000000]  67.78 38.49 0 top
T5  ADT2-1T-1P+  [ADT1-1WT]  83.41 30.57 90 top
T6  -  [MABA-007159-000000]  25.96 58.31 270 top
T7  -  [MABA-007159-000000]  15.34 58.31 270 top
T8  TCM4-19+  [DB714]  13.74 85.3 0 bottom
T9  TCM4-19+  [DB714]  13.74 58.09 180 bottom
U3  LMH6521  [32LLP_SQA32A]  14.24 71.69 0 bottom
U6  -  [FT245RL]  32.87 15.65 270 bottom
U7  LP5900SD-1.8/NOPB  [SC-MKT-SDB06A_6LLP]  26.21 9.69 0 top
U8  LP3878SD-ADJ  [SC-MKT-SDC08A_LLP]  77.44 102.04 270 top
U9  LP3878SD-ADJ  [SC-MKT-SDC08A_LLP]  32.2 35.55 0 top
U10  LP3878SD-ADJ  [SC-MKT-SDC08A_LLP]  31.82 48.63 0 top
U11  LP3878SD-ADJ  [SC-MKT-SDC08A_LLP]  102.51 14.92 270 top
U12  ADC16DX370 or LM97937  [QFN56_0P5]  62.97 71.69 0 top
U13  LMK04828BISQ  [SC-MKT-SQA64A]  83.41 45.12 0 top
U14  SN74AVC4T774  [TSSOP16_PW]  51.13 27.86 180 bottom
U15  SN74AVC4T774  [TSSOP16_PW]  22.1 34.34 270 bottom
U16  SN74AVC4T774  [TSSOP16_PW]  51.08 21.41 180 bottom
UNK+4V  Terminal_Block2  [MSTBA_RA_200_2]  10.16 29.21 0 top
UNK+5V  Terminal_Block2  [MSTBA_RA_200_2]  10.16 40.01 0 top
USB  USB_MINI_AB_MNE20-5G5P10  [CON_SMRT_USBMNE20_F]  37.17 4.57 90 top
V_VCXO3P3  TP, RED  [TP_500X_50]  104.86 32.1 0 top
V_XO3P3  TP, RED  [TP_500X_50]  96.05 20.97 0 top
VA1P2  TP, RED  [TP_500X_50]  52.05 97.54 0 top
VA1P8  TP, RED  [TP_500X_50]  48.37 32.38 0 top
VA3.0  TP, RED  [TP_500X_50]  48.23 42.88 270 top
VA3.0_LED  TP, RED  [TP_500X_50]  48.23 47.7 270 top
VAMP  TP, RED  [TP_500X_50]  22.86 71.69 0 top
VCMA  HDR-1x1_0  [TP_500X_50]  32.88 88.8 0 top
VCMB  HDR-1x1_0  [TP_500X_50]  32.88 54.58 0 top
VD1P2  TP, RED  [TP_500X_50]  59.67 97.66 0 top
VINA+  CLK_DIFF  [CON_SMA-EDGE]  1.91 91.3 0 top
VINA-  CLK_DIFF  [CON_SMA-EDGE]  1.91 78.86 0 top
VINB+  CLK_DIFF  [CON_SMA-EDGE]  1.91 52.09 0 top
VINB-  CLK_DIFF  [CON_SMA-EDGE]  1.91 64.53 0 top
VLMK3P3  TP, RED  [TP_500X_50]  85.48 18.99 0 top
VSPI1.8  TP, RED  [TP_500X_50]  19.74 15.57 0 top
Y1  CCHD-950-61.44  [SOIC6_100_WG272_L560]  94.53 30.21 90 bottom
Y2  CWX823-012.288M  [CWX813]  94.53 30.21 90 bottom
Y3  CVHD-950-122.88  [SOIC6_100_WG272_L560]  97.97 44.63 90 bottom
Z1  NFM41PC204F1H3  [NFM41P]  30.26 13.54 270 top
Z2  NFM41PC204F1H3  [NFM41P]  4.96 24.84 90 bottom
Z3  NFM41PC204F1H3  [NFM41P]  19.74 10.2 90 top
Z4  NFM41PC204F1H3  [NFM41P]  56.03 103.26 270 top
Z6  NFM41PC204F1H3  [NFM41P]  63.65 103.26 270 top
Z7  NFM41PC204F1H3  [NFM41P]  42.65 32.38 0 top
Z9  NFM41PC204F1H3  [NFM41P]  42.69 42.88 0 top
Z11  NFM41PC204F1H3  [NFM41P]  85.48 13.45 90 top
Z12  NFM41PC204F1H3  [NFM41P]  96.05 15.44 90 top
Z13  NFM41PC204F1H3  [NFM41P]  104.86 26.56 90 top
Z14  NFM41PC204F1H3  [NFM41P]  42.69 47.7 0 top
Z17  NFM41PC204F1H3  [NFM41P]  10.16 47.22 90 bottom

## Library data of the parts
BP2.5 CLKIN_SEL0 CLKIN_SEL1 GND GND1 GND1.2 GND1.8 GND2 GND3.0 STATUS_LD1 STATUS_LD2 V_VCXO3P3 V_XO3P3 VA1P2 VA1P8 VA3.0 VA3.0_LED VAMP VCMA VCMB VD1P2 VLMK3P3 VSPI1.8 = HDR-1x1_2
C1-C6 C25 C27 C97 C114 C115 C117 C118 C150 C151 C160 C161 C163 C164 C167 C174 C182 C207 C209 C217 C226 C228 C236 C238 C240 C242 = Capacitor_4
C7 C8 C10 C12 C61 C62 C64-C75 C77-C82 C84 C85 C87-C90 C92-C96 C131-C134 C139 C140 C148 C149 C158 C159 C162 C168 C183-C187 C200 C203 C210 C213 C222 C232 = Cap_1
C9 C11 C180 C181 C190-C195 C202 C204 C212 C214 C221 C223 C231 C234 = Capacitor_0
C13-C16 C20-C24 C26 C28-C31 C40-C51 C113 C120 C121 C146 C147 C205 C215 C224 C233 = Capacitor_3
C60 C63 C76 C86 C91 C130 C135 C138 = CAPACITOR NON-POL
C98 C116 C119 C169 C201 C206 C208 C211 C216 C220 C225 C227 C230 C235 C237 C239 C241 = Cap_Polar_1
C100-C112 C136 C137 C141-C145 C152-C157 C165 C166 C170-C173 = C-NON-POL
CLK EXTREF REFCLK SYSREF VINA+ VINA- VINB+ VINB- = SMA_CONN_5
FMC = ASP-134488-01_0
J1-J3 = HDR-1x4_0
JP1 = Jumper_1x3_100_0
JP2 = HDR-1x2_0
L1-L12 = INDUCTOR
L20-L28 = INDUCTOR FERRITE/SM
LMK_RESET LMK_SYNC SYSREF_SW = PUSH_BUTTON_0
LMKSPI = HDR-2x5
MT1-MT6 = TEST POINT
OVRA/TRIGRDY OVRB/TRIGGER SYNC = LED
Q2-Q4 = BSS138/SOT
R1-R17 R20-R40 R50-R58 R60-R83 R90-R104 R107-R112 R119-R145 R159 R169 R176 R217-R221 R234 = Resistor_3
R146-R153 R155 R156 R160-R168 R170 R171 R175 R177-R181 R235 R236 = Resistor_0
T1-T4 T6 T7 = MABA-007159-000000
T5 = ADT2-1T-1P+_0
T8 T9 = TCM4-19+_0
U3 = LMH6517_4
U6 = FT245RL
U7 = LP5900SD-??_1
U8-U11 = LP3878MR-ADJ_1
U12 = LM97937_SOCKET_4
U13 = LMK04828BISQ
U14-U16 = SN74AVC4T774
UNK+4V = Terminal_Block4_0
UNK+5V = Terminal_Block4_30
USB = USB_MINI_AB_MNE20-5G5P10
Y1 = CCHD-950-61.44
Y2 = CWX823-012.288M
Y3 = CVHD-950-122.88
Z1-Z4 Z6 Z7 Z9 Z11-Z14 Z17 = NFM41_0

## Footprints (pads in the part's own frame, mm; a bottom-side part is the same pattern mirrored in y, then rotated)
32LLP_SQA32A
  rect 0.599x0.249 smd: 1(-2.4,1.75) 2(-2.4,1.25) 3(-2.4,0.75) 4(-2.4,0.25) 5(-2.4,-0.25) 6(-2.4,-0.75) 7(-2.4,-1.25) 8(-2.4,-1.75) 17(2.4,-1.75) 18(2.4,-1.25) 19(2.4,-0.75) 20(2.4,-0.25) 21(2.4,0.25) 22(2.4,0.75) 23(2.4,1.25) 24(2.4,1.75)
  rect 0.249x0.599 smd: 9(-1.75,-2.4) 10(-1.25,-2.4) 11(-0.75,-2.4) 12(-0.25,-2.4) 13(0.25,-2.4) 14(0.75,-2.4) 15(1.25,-2.4) 16(1.75,-2.4) 25(1.75,2.4) 26(1.25,2.4) 27(0.75,2.4) 28(0.25,2.4) 29(-0.25,2.4) 30(-0.75,2.4) 31(-1.25,2.4) 32(-1.75,2.4)
  rect 3x3 smd: DAP(0,0)
0201
  rect 0.432x0.381 smd: 1(-0.356,0) 2(0.356,0)
0402
  rect 0.508x0.508 smd: 1(-0.635,0) 2(0.381,0)
0508
  rect 0.762x2.286 smd: 1(-0.762,0) 2(0.762,0)
0603
  rect 0.889x0.762 smd: 1(-0.635,0) 2(0.635,0)
0805
  rect 1.372x1.372 smd: 1(-1.003,0) 2(1.003,0)
ADT1-1WT
  rect 2.54x1.651 smd: 1(-2.54,2.54) 2(-2.54,0) 3(-2.54,-2.54) 4(2.54,-2.54) 5(2.54,0) 6(2.54,2.54)
BLKCON_2X1
  rect 1.524x1.524 hole 0.914: 1(0,1.27)
  round 1.524 hole 0.914: 2(0,-1.27)
BLKCON_4X1
  rect 1.473x1.473 hole 0.94: 1(0,3.81)
  round 1.473 hole 0.94: 2(0,1.27) 3(0,-1.27) 4(0,-3.81)
BLKCON_5X2
  rect 1.473x1.473 hole 0.94: 1(-1.27,5.08)
  round 1.473 hole 0.94: 2(1.27,5.08) 3(-1.27,2.54) 4(1.27,2.54) 5(-1.27,0) 6(1.27,0) 7(-1.27,-2.54) 8(1.27,-2.54) 9(-1.27,-5.08) 10(1.27,-5.08)
C0201_NO_SS
  rect 0.254x0.305 smd: 1(-0.318,0) 2(0.318,0)
C0402_NO_SS
  rect 0.406x0.508 smd: 1(-0.508,0) 2(0.508,0)
CAP_A-CASE
  rect 1.524x1.27 smd: 1(-1.27,0) 2(1.27,0)
COILCRAFT_SIZE0402HP
  rect 0.356x0.66 smd: 1(-0.432,0) 2(0.432,0)
COILCRAFT_SIZE0603CS
  rect 0.635x1.016 smd: 1(-0.635,0) 2(0.635,0)
COILCRAFT_SIZE0603LS
  rect 0.635x1.016 smd: 1(-0.635,0) 2(0.635,0)
CON_SMA-EDGE
  rect 3.556x0.635 smd: 1(0,0)
  rect 5.334x2.032 smd: 2(0.889,4.255) 3(0.889,-4.255) 4(0.889,-4.255) 5(0.889,4.255)
CON_SMRT_USBMNE20_F
  round 1.194 hole 1.168 unplated: (0.65,2.2) (0.65,-2.2)
  rect 2.311x0.508 smd: 1(3.45,1.6) 2(3.45,0.8) 3(3.45,0) 4(3.45,-0.8) 5(3.45,-1.6)
  rect 2.489x2.007 smd: 6(-2.15,-4.45) 7(3.35,-4.45) 8(3.35,4.45) 9(-2.15,4.45)
CONN_SEAM_040
  round 1.27 hole 1.295 unplated: (-27.191,0) (27.191,3.048)
  round 0.635 smd: A1(-24.765,-5.715) A2(-23.495,-5.715) A3(-22.225,-5.715) A4(-20.955,-5.715) A5(-19.685,-5.715) A6(-18.415,-5.715) A7(-17.145,-5.715) A8(-15.875,-5.715) A9(-14.605,-5.715) A10(-13.335,-5.715) A11(-12.065,-5.715) A12(-10.795,-5.715) A13(-9.525,-5.715) A14(-8.255,-5.715) A15(-6.985,-5.715) A16(-5.715,-5.715) A17(-4.445,-5.715) A18(-3.175,-5.715) A19(-1.905,-5.715) A20(-0.635,-5.715) A21(0.635,-5.715) A22(1.905,-5.715) A23(3.175,-5.715) A24(4.445,-5.715) A25(5.715,-5.715) A26(6.985,-5.715) A27(8.255,-5.715) A28(9.525,-5.715) A29(10.795,-5.715) A30(12.065,-5.715) A31(13.335,-5.715) A32(14.605,-5.715) A33(15.875,-5.715) A34(17.145,-5.715) A35(18.415,-5.715) A36(19.685,-5.715) A37(20.955,-5.715) A38(22.225,-5.715) A39(23.495,-5.715) A40(24.765,-5.715) B1(-24.765,-4.445) B2(-23.495,-4.445) B3(-22.225,-4.445) B4(-20.955,-4.445) B5(-19.685,-4.445) B6(-18.415,-4.445) B7(-17.145,-4.445) B8(-15.875,-4.445) B9(-14.605,-4.445) B10(-13.335,-4.445) B11(-12.065,-4.445) B12(-10.795,-4.445) B13(-9.525,-4.445) B14(-8.255,-4.445) B15(-6.985,-4.445) B16(-5.715,-4.445) B17(-4.445,-4.445) B18(-3.175,-4.445) B19(-1.905,-4.445) B20(-0.635,-4.445) B21(0.635,-4.445) B22(1.905,-4.445) B23(3.175,-4.445) B24(4.445,-4.445) B25(5.715,-4.445) B26(6.985,-4.445) B27(8.255,-4.445) B28(9.525,-4.445) B29(10.795,-4.445) B30(12.065,-4.445) B31(13.335,-4.445) B32(14.605,-4.445) B33(15.875,-4.445) B34(17.145,-4.445) B35(18.415,-4.445) B36(19.685,-4.445) B37(20.955,-4.445) B38(22.225,-4.445) B39(23.495,-4.445) B40(24.765,-4.445) C1(-24.765,-3.175) C2(-23.495,-3.175) C3(-22.225,-3.175) C4(-20.955,-3.175) C5(-19.685,-3.175) C6(-18.415,-3.175) C7(-17.145,-3.175) C8(-15.875,-3.175) C9(-14.605,-3.175) C10(-13.335,-3.175) C11(-12.065,-3.175) C12(-10.795,-3.175) C13(-9.525,-3.175) C14(-8.255,-3.175) C15(-6.985,-3.175) C16(-5.715,-3.175) C17(-4.445,-3.175) C18(-3.175,-3.175) C19(-1.905,-3.175) C20(-0.635,-3.175) C21(0.635,-3.175) C22(1.905,-3.175) C23(3.175,-3.175) C24(4.445,-3.175) C25(5.715,-3.175) C26(6.985,-3.175) C27(8.255,-3.175) C28(9.525,-3.175) C29(10.795,-3.175) C30(12.065,-3.175) C31(13.335,-3.175) C32(14.605,-3.175) C33(15.875,-3.175) C34(17.145,-3.175) C35(18.415,-3.175) C36(19.685,-3.175) C37(20.955,-3.175) C38(22.225,-3.175) C39(23.495,-3.175) C40(24.765,-3.175) D1(-24.765,-1.905) D2(-23.495,-1.905) D3(-22.225,-1.905) D4(-20.955,-1.905) D5(-19.685,-1.905) D6(-18.415,-1.905) D7(-17.145,-1.905) D8(-15.875,-1.905) D9(-14.605,-1.905) D10(-13.335,-1.905) D11(-12.065,-1.905) D12(-10.795,-1.905) D13(-9.525,-1.905) D14(-8.255,-1.905) D15(-6.985,-1.905) D16(-5.715,-1.905) D17(-4.445,-1.905) D18(-3.175,-1.905) D19(-1.905,-1.905) D20(-0.635,-1.905) D21(0.635,-1.905) D22(1.905,-1.905) D23(3.175,-1.905) D24(4.445,-1.905) D25(5.715,-1.905) D26(6.985,-1.905) D27(8.255,-1.905) D28(9.525,-1.905) D29(10.795,-1.905) D30(12.065,-1.905) D31(13.335,-1.905) D32(14.605,-1.905) D33(15.875,-1.905) D34(17.145,-1.905) D35(18.415,-1.905) D36(19.685,-1.905) D37(20.955,-1.905) D38(22.225,-1.905) D39(23.495,-1.905) D40(24.765,-1.905) E1(-24.765,-0.635) E2(-23.495,-0.635) E3(-22.225,-0.635) E4(-20.955,-0.635) E5(-19.685,-0.635) E6(-18.415,-0.635) E7(-17.145,-0.635) E8(-15.875,-0.635) E9(-14.605,-0.635) E10(-13.335,-0.635) E11(-12.065,-0.635) E12(-10.795,-0.635) E13(-9.525,-0.635) E14(-8.255,-0.635) E15(-6.985,-0.635) E16(-5.715,-0.635) E17(-4.445,-0.635) E18(-3.175,-0.635) E19(-1.905,-0.635) E20(-0.635,-0.635) E21(0.635,-0.635) E22(1.905,-0.635) E23(3.175,-0.635) E24(4.445,-0.635) E25(5.715,-0.635) E26(6.985,-0.635) E27(8.255,-0.635) E28(9.525,-0.635) E29(10.795,-0.635) E30(12.065,-0.635) E31(13.335,-0.635) E32(14.605,-0.635) E33(15.875,-0.635) E34(17.145,-0.635) E35(18.415,-0.635) E36(19.685,-0.635) E37(20.955,-0.635) E38(22.225,-0.635) E39(23.495,-0.635) E40(24.765,-0.635) F1(-24.765,0.635) F2(-23.495,0.635) F3(-22.225,0.635) F4(-20.955,0.635) F5(-19.685,0.635) F6(-18.415,0.635) F7(-17.145,0.635) F8(-15.875,0.635) F9(-14.605,0.635) F10(-13.335,0.635) F11(-12.065,0.635) F12(-10.795,0.635) F13(-9.525,0.635) F14(-8.255,0.635) F15(-6.985,0.635) F16(-5.715,0.635) F17(-4.445,0.635) F18(-3.175,0.635) F19(-1.905,0.635) F20(-0.635,0.635) F21(0.635,0.635) F22(1.905,0.635) F23(3.175,0.635) F24(4.445,0.635) F25(5.715,0.635) F26(6.985,0.635) F27(8.255,0.635) F28(9.525,0.635) F29(10.795,0.635) F30(12.065,0.635) F31(13.335,0.635) F32(14.605,0.635) F33(15.875,0.635) F34(17.145,0.635) F35(18.415,0.635) F36(19.685,0.635) F37(20.955,0.635) F38(22.225,0.635) F39(23.495,0.635) F40(24.765,0.635) G1(-24.765,1.905) G2(-23.495,1.905) G3(-22.225,1.905) G4(-20.955,1.905) G5(-19.685,1.905) G6(-18.415,1.905) G7(-17.145,1.905) G8(-15.875,1.905) G9(-14.605,1.905) G10(-13.335,1.905) G11(-12.065,1.905) G12(-10.795,1.905) G13(-9.525,1.905) G14(-8.255,1.905) G15(-6.985,1.905) G16(-5.715,1.905) G17(-4.445,1.905) G18(-3.175,1.905) G19(-1.905,1.905) G20(-0.635,1.905) G21(0.635,1.905) G22(1.905,1.905) G23(3.175,1.905) G24(4.445,1.905) G25(5.715,1.905) G26(6.985,1.905) G27(8.255,1.905) G28(9.525,1.905) G29(10.795,1.905) G30(12.065,1.905) G31(13.335,1.905) G32(14.605,1.905) G33(15.875,1.905) G34(17.145,1.905) G35(18.415,1.905) G36(19.685,1.905) G37(20.955,1.905) G38(22.225,1.905) G39(23.495,1.905) G40(24.765,1.905) H1(-24.765,3.175) H2(-23.495,3.175) H3(-22.225,3.175) H4(-20.955,3.175) H5(-19.685,3.175) H6(-18.415,3.175) H7(-17.145,3.175) H8(-15.875,3.175) H9(-14.605,3.175) H10(-13.335,3.175) H11(-12.065,3.175) H12(-10.795,3.175) H13(-9.525,3.175) H14(-8.255,3.175) H15(-6.985,3.175) H16(-5.715,3.175) H17(-4.445,3.175) H18(-3.175,3.175) H19(-1.905,3.175) H20(-0.635,3.175) H21(0.635,3.175) H22(1.905,3.175) H23(3.175,3.175) H24(4.445,3.175) H25(5.715,3.175) H26(6.985,3.175) H27(8.255,3.175) H28(9.525,3.175) H29(10.795,3.175) H30(12.065,3.175) H31(13.335,3.175) H32(14.605,3.175) H33(15.875,3.175) H34(17.145,3.175) H35(18.415,3.175) H36(19.685,3.175) H37(20.955,3.175) H38(22.225,3.175) H39(23.495,3.175) H40(24.765,3.175) J1(-24.765,4.445) J2(-23.495,4.445) J3(-22.225,4.445) J4(-20.955,4.445) J5(-19.685,4.445) J6(-18.415,4.445) J7(-17.145,4.445) J8(-15.875,4.445) J9(-14.605,4.445) J10(-13.335,4.445) J11(-12.065,4.445) J12(-10.795,4.445) J13(-9.525,4.445) J14(-8.255,4.445) J15(-6.985,4.445) J16(-5.715,4.445) J17(-4.445,4.445) J18(-3.175,4.445) J19(-1.905,4.445) J20(-0.635,4.445) J21(0.635,4.445) J22(1.905,4.445) J23(3.175,4.445) J24(4.445,4.445) J25(5.715,4.445) J26(6.985,4.445) J27(8.255,4.445) J28(9.525,4.445) J29(10.795,4.445) J30(12.065,4.445) J31(13.335,4.445) J32(14.605,4.445) J33(15.875,4.445) J34(17.145,4.445) J35(18.415,4.445) J36(19.685,4.445) J37(20.955,4.445) J38(22.225,4.445) J39(23.495,4.445) J40(24.765,4.445) K1(-24.765,5.715) K2(-23.495,5.715) K3(-22.225,5.715) K4(-20.955,5.715) K5(-19.685,5.715) K6(-18.415,5.715) K7(-17.145,5.715) K8(-15.875,5.715) K9(-14.605,5.715) K10(-13.335,5.715) K11(-12.065,5.715) K12(-10.795,5.715) K13(-9.525,5.715) K14(-8.255,5.715) K15(-6.985,5.715) K16(-5.715,5.715) K17(-4.445,5.715) K18(-3.175,5.715) K19(-1.905,5.715) K20(-0.635,5.715) K21(0.635,5.715) K22(1.905,5.715) K23(3.175,5.715) K24(4.445,5.715) K25(5.715,5.715) K26(6.985,5.715) K27(8.255,5.715) K28(9.525,5.715) K29(10.795,5.715) K30(12.065,5.715) K31(13.335,5.715) K32(14.605,5.715) K33(15.875,5.715) K34(17.145,5.715) K35(18.415,5.715) K36(19.685,5.715) K37(20.955,5.715) K38(22.225,5.715) K39(23.495,5.715) K40(24.765,5.715)
CWX813
  rect 2x1.8 smd: 1(-2.095,2.54) 2(-2.095,-2.54) 3(2.095,-2.54) 4(2.095,2.54)
DB714
  rect 0.762x1.651 smd: 1(-1.27,1.587) 2(0,1.587) 3(1.27,1.587) 4(1.27,-1.587) 5(0,-1.587) 6(-1.27,-1.587)
EVQPPD
  rect 2x1 smd: 1(-3,0) 2(3,0)
FT245RL
  oval 2.108x0.406 smd: 1(-3.45,4.225) 2(-3.45,3.575) 3(-3.45,2.925) 4(-3.45,2.275) 5(-3.45,1.625) 6(-3.45,0.975) 7(-3.45,0.325) 8(-3.45,-0.325) 9(-3.45,-0.975) 10(-3.45,-1.625) 11(-3.45,-2.275) 12(-3.45,-2.925) 13(-3.45,-3.575) 14(-3.45,-4.225) 15(3.45,-4.225) 16(3.45,-3.575) 17(3.45,-2.925) 18(3.45,-2.275) 19(3.45,-1.625) 20(3.45,-0.975) 21(3.45,-0.325) 22(3.45,0.325) 23(3.45,0.975) 24(3.45,1.625) 25(3.45,2.275) 26(3.45,2.925) 27(3.45,3.575) 28(3.45,4.225)
HDR_THVT_1X3_100_M
  rect 1.473x1.473 hole 0.965: 1(0,0)
  round 1.473 hole 0.965: 2(0,-2.54) 3(0,-5.08)
LED_0805
  rect 1.422x1.524 smd: 1(-1.143,0) 2(1.143,0)
MABA-007159-000000
  rect 0.762x1.397 smd: 1(-1.27,1.714) 2(0,1.714) 3(1.27,1.714) 4(1.27,-1.714) 5(0,-1.714) 6(-1.27,-1.714)
MSTBA_RA_200_2
  round 1.981 hole 1.422: 1(0,2.54) 2(0,-2.54)
NFM41P
  rect 1.27x1.6 smd: 1(-2.413,0) 3(2.413,0)
  rect 1.778x2.54 smd: 2(0,0)
QFN56_0P5
  round 1.52 hole 1.52 unplated: (-8,12)
  custom 0.07x0.07 smd: 1(-3.69,3.25) 2(-3.69,2.75) 3(-3.69,2.25) 4(-3.69,1.75) 5(-3.69,1.25) 6(-3.69,0.75) 7(-3.69,0.25) 8(-3.69,-0.25) 9(-3.69,-0.75) 10(-3.69,-1.25) 11(-3.69,-1.75) 12(-3.69,-2.25) 13(-3.69,-2.75) 14(-3.69,-3.25) 15(-3.25,-3.69) 16(-2.75,-3.69) 17(-2.25,-3.69) 18(-1.75,-3.69) 19(-1.25,-3.69) 20(-0.75,-3.69) 21(-0.25,-3.69) 22(0.25,-3.69) 23(0.75,-3.69) 24(1.25,-3.69) 25(1.75,-3.69) 26(2.25,-3.69) 27(2.75,-3.69) 28(3.25,-3.69) 29(3.69,-3.25) 30(3.69,-2.75) 31(3.69,-2.25) 32(3.69,-1.75) 33(3.69,-1.25) 34(3.69,-0.75) 35(3.69,-0.25) 36(3.69,0.25) 37(3.69,0.75) 38(3.69,1.25) 39(3.69,1.75) 40(3.69,2.25) 41(3.69,2.75) 42(3.69,3.25) 43(3.25,3.69) 44(2.75,3.69) 45(2.25,3.69) 46(1.75,3.69) 47(1.25,3.69) 48(0.75,3.69) 49(0.25,3.69) 50(-0.25,3.69) 51(-0.75,3.69) 52(-1.25,3.69) 53(-1.75,3.69) 54(-2.25,3.69) 55(-2.75,3.69) 56(-3.25,3.69)
  rect 6.6x6.6 smd: 57(0,0)
R0603
  rect 0.813x0.965 smd: 1(-0.711,0) 2(0.711,0)
SC-MKT-SDB06A_6LLP
  rect 0.61x0.254 smd: 1(-1.143,0.66) 2(-1.143,0) 3(-1.143,-0.66) 4(1.143,-0.66) 5(1.143,0) 6(1.143,0.66)
  rect 0.762x1.194 smd: 7(0,0)
SC-MKT-SDC08A_LLP
  rect 0.599x0.3 smd: 1(-1.9,1.199) 2(-1.9,0.399) 3(-1.9,-0.399) 4(-1.9,-1.199) 5(1.9,-1.199) 6(1.9,-0.399) 7(1.9,0.399) 8(1.9,1.199)
  rect 2.591x2.997 smd: DAP(0,0)
SC-MKT-SQA64A
  rect 0.599x0.249 smd: 1(-4.394,3.759) 2(-4.394,3.251) 3(-4.394,2.743) 4(-4.394,2.261) 5(-4.394,1.753) 6(-4.394,1.245) 7(-4.394,0.762) 8(-4.394,0.254) 9(-4.394,-0.254) 10(-4.394,-0.762) 11(-4.394,-1.245) 12(-4.394,-1.753) 13(-4.394,-2.261) 14(-4.394,-2.743) 15(-4.394,-3.251) 16(-4.394,-3.759) 33(4.394,-3.759) 34(4.394,-3.251) 35(4.394,-2.743) 36(4.394,-2.261) 37(4.394,-1.753) 38(4.394,-1.245) 39(4.394,-0.762) 40(4.394,-0.254) 41(4.394,0.254) 42(4.394,0.762) 43(4.394,1.245) 44(4.394,1.753) 45(4.394,2.261) 46(4.394,2.743) 47(4.394,3.251) 48(4.394,3.759)
  rect 0.249x0.599 smd: 17(-3.759,-4.394) 18(-3.251,-4.394) 19(-2.743,-4.394) 20(-2.261,-4.394) 21(-1.753,-4.394) 22(-1.245,-4.394) 23(-0.762,-4.394) 24(-0.254,-4.394) 25(0.254,-4.394) 26(0.762,-4.394) 27(1.245,-4.394) 28(1.753,-4.394) 29(2.261,-4.394) 30(2.743,-4.394) 31(3.251,-4.394) 32(3.759,-4.394) 49(3.759,4.394) 50(3.251,4.394) 51(2.743,4.394) 52(2.261,4.394) 53(1.753,4.394) 54(1.245,4.394) 55(0.762,4.394) 56(0.254,4.394) 57(-0.254,4.394) 58(-0.762,4.394) 59(-1.245,4.394) 60(-1.753,4.394) 61(-2.261,4.394) 62(-2.743,4.394) 63(-3.251,4.394) 64(-3.759,4.394)
  rect 7.188x7.188 smd: 65(0,0)
SMD_SIZE0402
  rect 0.635x0.508 smd: 1(-0.635,0) 2(0.635,0)
SMD_SIZE0603
  rect 0.762x0.965 smd: 1(-0.813,0) 2(0.813,0)
SMD_SIZE1206
  rect 1.27x1.778 smd: 1(-1.397,0) 2(1.397,0)
SMD_SIZE3216
  rect 1.524x1.27 smd: 1(-1.27,0) 2(1.27,0)
SOIC6_100_WG272_L560
  rect 4.699x1.397 smd: 1(-3.454,2.54) 2(-3.454,0) 3(-3.454,-2.54) 4(3.454,-2.54) 5(3.454,0) 6(3.454,2.54)
SOT-723
  rect 0.4x0.45 smd: 1(-0.4,-0.575) 2(0.4,-0.575)
  rect 0.5x0.45 smd: 3(0,0.575)
TP_500X_50
  round 2.21 hole 1.6: 1(0,0)
TSSOP16_PW
  rect 1.45x0.25 smd: 1(-2.975,2.275) 2(-2.975,1.625) 3(-2.975,0.975) 4(-2.975,0.325) 5(-2.975,-0.325) 6(-2.975,-0.975) 7(-2.975,-1.625) 8(-2.975,-2.275) 9(2.975,-2.275) 10(2.975,-1.625) 11(2.975,-0.975) 12(2.975,-0.325) 13(2.975,0.325) 14(2.975,0.975) 15(2.975,1.625) 16(2.975,2.275)
unnamed#2
  round 1.016 smd: (0,0)
VIA85D55
  round 6.35 hole 3.175: 1(0,0)

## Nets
+4V: C201.1 C202.1 C211.1 C212.1 C220.1 C221.1 C230.1 C231.1 R168.1 R175.1 R179.2 R180.2 R181.1 R235.1 R236.1 U8.4(IN) U9.4(IN) U10.4(IN) U11.4(IN) UNK+4V.1
GND: C3.2 C6.2 C7.2 C8.2 C9.2 C10.2 C11.2 C12.2 C13.2 C14.1 C15.2 C16.1 C24.1 C25.2 C26.1 C27.2 C44.2 C45.1 C50.2 C51.1 C60.1 C61.2 C62.2 C63.1 C64.2 C65.2 C66.2 C67.2 C68.2 C69.2 C70.2 C71.2 C72.1 C73.1 C74.1 C75.1 C76.1 C77.1 C78.1 C79.2 C80.2 C81.2 C82.2 C84.2 C85.2 C86.1 C87.2 C88.2 C89.1 C90.1 C91.2 C92.2 C93.2 C94.1 C95.1 C96.2 C97.1 C98.2 C112.2 C113.1 C114.2 C115.2 C116.2 C117.2 C118.2 C119.2 C120.1 C121.1 C130.2 C131.2 C132.2 C133.2 C134.2 C135.2 C136.2 C137.2 C138.2 C139.2 C140.2 C141.2 C142.2 C143.2 C144.2 C145.2 C146.1 C147.1 C148.2 C149.2 C151.2 C152.2 C154.2 C156.2 C160.2 C162.2 C163.2 C164.2 C167.2 C168.2 C169.2 C174.2 C190.1 C191.1 C192.1 C193.1 C194.1 C195.1 C200.1 C201.2 C202.2 C203.2 C204.2 C206.2 C207.2 C208.2 C209.2 C210.1 C211.2 C212.2 C213.2 C214.2 C216.2 C217.2 C220.2 C221.2 C222.2 C223.2 C225.2 C226.2 C227.2 C228.2 C230.2 C231.2 C232.2 C234.2 C235.2 C236.2 C237.2 C238.2 C239.2 C240.2 C241.2 C242.2 CLK.2(SHIELD2) CLK.3(SHIELD3) CLK.4(SHIELD4) CLK.5(SHIELD5) EXTREF.2(SHIELD2) EXTREF.3(SHIELD3) EXTREF.4(SHIELD4) EXTREF.5(SHIELD5) FMC.A1 FMC.A4 FMC.A5 FMC.A8 FMC.A9 FMC.A12 FMC.A13 FMC.A16 FMC.A17 FMC.A20 FMC.A21 FMC.A24 FMC.A25 FMC.A28 FMC.A29 FMC.A32 FMC.A33 FMC.A36 FMC.A37 FMC.A40 FMC.B2 FMC.B3 FMC.B6 FMC.B7 FMC.B10 FMC.B11 FMC.B14 FMC.B15 FMC.B18 FMC.B19 FMC.B22 FMC.B23 FMC.B26 FMC.B27 FMC.B30 FMC.B31 FMC.B34 FMC.B35 FMC.B38 FMC.B39 FMC.C1 FMC.C4 FMC.C5 FMC.C8 FMC.C9 FMC.C12 FMC.C13 FMC.C16 FMC.C17 FMC.C20 FMC.C21 FMC.C24 FMC.C25 FMC.C28 FMC.C29 FMC.C32 FMC.C33 FMC.C36 FMC.C38 FMC.C40 FMC.D2 FMC.D3 FMC.D6 FMC.D7 FMC.D10 FMC.D13 FMC.D16 FMC.D19 FMC.D22 FMC.D25 FMC.D28 FMC.D37 FMC.D39 FMC.E1 FMC.E4 FMC.E5 FMC.E8 FMC.E11 FMC.E14 FMC.E17 FMC.E20 FMC.E23 FMC.E26 FMC.E29 FMC.E32 FMC.E35 FMC.E38 FMC.E40 FMC.F2 FMC.F3 FMC.F6 FMC.F9 FMC.F12 FMC.F15 FMC.F18 FMC.F21 FMC.F24 FMC.F27 FMC.F30 FMC.F33 FMC.F36 FMC.F39 FMC.G1 FMC.G4 FMC.G5 FMC.G8 FMC.G11 FMC.G14 FMC.G17 FMC.G20 FMC.G23 FMC.G26 FMC.G29 FMC.G32 FMC.G35 FMC.G38 FMC.G40 FMC.H2 FMC.H3 FMC.H6 FMC.H9 FMC.H12 FMC.H15 FMC.H18 FMC.H21 FMC.H24 FMC.H27 FMC.H30 FMC.H33 FMC.H36 FMC.H39 FMC.J1 FMC.J4 FMC.J5 FMC.J8 FMC.J11 FMC.J14 FMC.J17 FMC.J20 FMC.J23 FMC.J26 FMC.J29 FMC.J32 FMC.J35 FMC.J38 FMC.J40 FMC.K2 FMC.K3 FMC.K6 FMC.K9 FMC.K12 FMC.K15 FMC.K18 FMC.K21 FMC.K24 FMC.K27 FMC.K30 FMC.K33 FMC.K36 FMC.K39 GND.1 GND1.1 GND1.2.1 GND1.8.1 GND3.0.1 L1.2 L2.2 L3.1 L4.1 Q2.2(S) Q3.2(S) Q4.2(S) R1.1 R2.2 R4.1 R5.1 R31.2 R32.2 R34.1 R35.1 R40.1 R52.2 R55.1 R56.1 R60.2 R67.2 R70.2 R71.2 R90.1 R91.1 R92.1 R93.1 R98.2 R99.2 R100.2 R101.1 R104.2 R107.1 R109.1 R111.1 R125.1 R145.2 R146.2 R148.2 R150.2 R153.2 R155.2 R159.2 R161.1 R163.2 R165.1 R167.2 R169.2 R171.2 R176.2 R178.2 R217.1 R218.1 REFCLK.2(SHIELD2) REFCLK.3(SHIELD3) REFCLK.4(SHIELD4) REFCLK.5(SHIELD5) SYSREF.2(SHIELD2) SYSREF.3(SHIELD3) SYSREF.4(SHIELD4) SYSREF.5(SHIELD5) T3.4 T4.4 T5.2 T5.3 T5.5 T8.2 T8.4 T9.2 T9.6 U3.3(A5/GND) U3.6(B5/GND) U3.7(B4/GND/UPB) U3.8(B3/GND/DNB) U3.9(B2/GND/S1B) U3.10(B1/GND/S0B) U3.13(GND_13) U3.15(GND_15) U3.16(B0/GND) U3.20(LATB/GND) U3.21(LATA/GND) U3.25(A0/GND) U3.26(GND_26) U3.28(GND_28) U3.DAP U8.3(GND) U8.DAP U9.3(GND) U9.DAP U10.3(GND) U10.DAP U11.3(GND) U11.DAP U12.3(AGND_3) U12.6(AGND_6) U12.9(AGND_9) U12.12(AGND_12) U12.16(AGND_16) U12.19(AGND_19) U12.22(AGND_22) U12.25(DGND_25) U12.31(AGND_31) U12.40(AGND_40) U12.46(DGND_46) U12.49(AGND_49) U12.52(AGND_52) U12.55(AGND_55) U12.57(DAP) U13.65(DAP) U14.1(DIR1) U14.2(DIR2) U14.7(DIR3) U14.9(OEB) U14.10(GND) U15.1(DIR1) U15.2(DIR2) U15.7(DIR3) U15.8(DIR4) U15.9(OEB) U15.10(GND) U15.11(B4) U16.1(DIR1) U16.2(DIR2) U16.8(DIR4) U16.10(GND) UNK+4V.2 UNK+5V.2 VINA+.2(SHIELD2) VINA+.3(SHIELD3) VINA+.4(SHIELD4) VINA+.5(SHIELD5) VINA-.2(SHIELD2) VINA-.3(SHIELD3) VINA-.4(SHIELD4) VINA-.5(SHIELD5) VINB+.2(SHIELD2) VINB+.3(SHIELD3) VINB+.4(SHIELD4) VINB+.5(SHIELD5) VINB-.2(SHIELD2) VINB-.3(SHIELD3) VINB-.4(SHIELD4) VINB-.5(SHIELD5) Y1.3(GND) Y2.2(GND) Y3.3(GND) Z2.2 Z2.3 Z4.2 Z6.2 Z7.2 Z9.2 Z11.2 Z12.2 Z13.2 Z14.2 Z17.2
GND2: C180.2 C181.2 C182.2 C183.2 C184.2 C185.2 C186.2 C187.2 GND2.1 U6.7(GND_7) U6.18(GND_18) U6.21(GND_21) U6.25(AGND) U6.26(TEST) U7.3(GND) U7.7(DAP) USB.5(GND) USB.6(GND1) USB.7(GND2) USB.8(GND3) USB.9(GND4) Z1.2 Z2.1 Z3.2
ADC_VCMA: C114.1 C115.1 C116.1 R16.2 U12.1(VCMA)
ADC_VCMB: C117.1 C118.1 C119.1 R27.2 U12.14(VCMB)
ADC_VINA+: R12.1 U12.4(VINA+)
ADC_VINA-: R13.1 U12.5(VINA-)
ADC_VINB+: R25.1 U12.11(VINB+)
ADC_VINB-: R24.1 U12.10(VINB-)
CLK_VIN+: C108.1 R72.2 R74.2 R76.2
CLK_VIN-: C109.1 R73.2 R75.2 R77.2
CLKIN+: C108.2 U12.17(CLKIN+)
CLKIN-: C109.2 U12.18(CLKIN-)
CLKOUT2+: C173.1 R93.2 U13.15(DCLKOUT2)
CLKOUT2-: C172.1 R92.2 U13.16(DCLKOUT2*)
CLKOUT3+: C171.1 R91.2 U13.13(SDCLKOUT3)
CLKOUT3-: C170.1 R90.2 U13.14(SDCLKOUT3*)
CLKOUT4+: C166.1 U13.24(DCLKOUT4)
CLKOUT4-: C165.1 U13.25(DCLKOUT4*)
CSB_ADC: R122.1 R128.2 U14.13(B2)
CSB_ADC_3P0: J3.2 R66.2 R135.2 U12.54(CSB)
CSB_LMH: R123.1 R129.2 U15.13(B2)
CSB_LMH_3P3: J1.2 R139.2 U3.32(A2/CS/S1A)
CSB_LMK: R124.1 R130.2 U16.13(B2)
CSB_LMK_3P3: J2.2 R142.2 R146.1 R147.1 U13.18(CS*)
DIR_LMK: R125.2 R133.2 U16.11(B4)
EXT_ ADC_CLK: R218.2 R219.1 R234.2
EXTREF_XO: C159.1 R108.2 R109.2 R110.1 R234.1
FILT_VINA+: C16.2 C31.1 C47.2 C48.2 L9.1
FILT_VINA-: C15.1 C30.1 C46.2 C48.1 L9.2
FILT_VINB+: C13.1 C28.1 C40.2 C42.1 L5.2
FILT_VINB-: C14.2 C29.1 C41.2 C42.2 L5.1
FILT_VOUTA+: C49.2 C51.2 L11.2 L12.1 R14.2
FILT_VOUTA-: C49.1 C50.1 L10.2 L12.2 R15.2
FILT_VOUTB+: C43.1 C44.1 L6.2 L8.2 R29.1
FILT_VOUTB-: C43.2 C45.2 L7.2 L8.1 R28.1
FMC_ADC_DEVCLK+: FMC.D8 R76.1
FMC_ADC_DEVCLK-: FMC.D9 R77.1
FMC_ADC_SYSREF+: FMC.D11 R83.1
FMC_ADC_SYSREF-: FMC.D12 R82.1
FMC_FPGA_DEVCLKA+: FMC.D4 U13.51(DCLKOUT8)
FMC_FPGA_DEVCLKA-: FMC.D5 U13.52(DCLKOUT8*)
FMC_FPGA_DEVCLKB+: FMC.G6 U13.54(DCLKOUT10)
FMC_FPGA_DEVCLKB-: FMC.G7 U13.55(DCLKOUT10*)
FMC_FPGA_SYSREF+: FMC.G9 U13.56(SDCLKOUT11)
FMC_FPGA_SYSREF-: FMC.G10 U13.57(SDCLKOUT11*)
INA+: R8.2 T2.1
INA-: R9.2 T2.3
INB+: R21.2 T6.3
INB-: R20.2 T6.1
LMH_VINA: R3.2 T8.6
LMH_VINB: R6.1 T9.4
LMK_ADC_DEVCLK+: C172.2 R74.1
LMK_ADC_DEVCLK-: C173.2 R75.1
LMK_ADC_SYSREF+: C170.2 R81.1
LMK_ADC_SYSREF-: C171.2 R80.1
LMK_DIR: R144.2 U16.7(DIR3)
LMK_VCC1/5/6: C130.1 C131.1 C132.1 C133.1 L20.1 U13.10(VCC1_VCO) U13.33(VCC5_DIG) U13.36(VCC6_PLL1)
LMK_VCC2: C141.1 L24.2 U13.17(VCC2_CG1)
LMK_VCC3: C142.1 L25.2 U13.21(VCC3_SYSREF)
LMK_VCC4: C143.1 L26.2 U13.26(VCC4_CG2)
LMK_VCC7: C136.1 L22.2 U13.39(VCC7_OSCOUT)
LMK_VCC8/10: C138.1 C139.1 C140.1 L21.1 L22.1 L23.1 U13.42(VCC8_OSCIN) U13.47(VCC10_PLL2)
LMK_VCC9: C137.1 L23.2 U13.45(VCC9_CP2)
LMK_VCC11: C144.1 L27.2 U13.53(VCC11_CG3)
LMK_VCC12: C145.1 L28.2 U13.64(VCC12_CG0)
OVRA/TRIGRDY: FMC.G27 R53.2
OVRB/TRIGGER: FMC.D26 R54.2
PG_C2M: FMC.D1 R60.1
PG_M2C: FMC.F1 R61.1
REFCLK+: C166.2 T5.6
REFCLK-: C165.2 T5.4
RESET_LMK_3P3: R95.1 R152.2 R153.1
SA0+: C101.1 FMC.A3
SA0-: C100.1 FMC.A2
SA1+: C103.1 FMC.C7
SA1-: C102.1 FMC.C6
SA_0+: C101.2 U12.38(SA0+)
SA_0-: C100.2 U12.39(SA0-)
SA_1+: C103.2 U12.36(SA1+)
SA_1-: C102.2 U12.37(SA1-)
SB0+: C107.1 FMC.A11
SB0-: C106.1 FMC.A10
SB1+: C105.1 FMC.A7
SB1-: C104.1 FMC.A6
SB_0+: C107.2 U12.32(SB0+)
SB_0-: C106.2 U12.33(SB0-)
SB_1+: C105.2 U12.34(SB1+)
SB_1-: C104.2 U12.35(SB1-)
SCLK_ADC_3P0: J3.1 R65.2 R134.2 U12.53(SCLK)
SCLK_ADC_LMH_LMK: R126.2 U14.14(B1) U15.14(B1) U16.14(B1)
SCLK_LMH_3P3: J1.1 R138.2 U3.2(A4/CLK/UPA)
SCLK_LMK_3P3: J2.1 R141.2 R150.1 R151.1 U13.19(SCK)
SDI_ADC_3P0: J3.3 R63.1 R136.2 U12.47(SDI)
SDI_ADC_LMH: R127.2 U14.12(B3) U15.12(B3)
SDI_LMH_3P3: J1.3 R140.2 U3.1(A3/SDI/DNA)
SDIO_LMK: R132.2 U16.12(B3)
SDIO_LMK_3P3: J2.3 J2.4 R143.2 R148.1 R149.1 U13.20(SDIO)
SDO_ADC: R131.2 U14.11(B4)
SDO_ADC_3P0: J3.4 R64.1 R137.2 U12.48(SDO)
SYNC_LMK_3P3: R96.1 R155.1 R156.2
SYNCB+: FMC.G12 U12.27(SYNCB+)
SYNCB-: FMC.G13 U12.28(SYNCB-)
SYSREF+: C110.2 R51.1 U12.23(SYSREF+)
SYSREF-: C111.2 C112.1 U12.24(SYSREF-)
SYSREF_VIN+: C110.1 R50.2 R78.2 R81.2 R83.2
SYSREF_VIN-: C111.1 R50.1 R79.2 R80.2 R82.2
V_VCXO3.3: C163.1 C164.1 C169.1 C174.1 C239.1 C240.1 V_VCXO3P3.1 Y3.6(VS) Z13.3
V_XO3.3: C167.1 C237.1 C238.1 R112.2 V_XO3P3.1 Y1.6(VS) Y2.4(VCC) Z12.3
VA1.2: C63.2 C64.1 C65.1 C74.2 C75.2 C76.2 C84.1 C85.1 C91.1 C92.1 C93.1 C206.1 C207.1 SYSREF_SW.1 U12.8(VA1.2_8) U12.21(VA1.2_21) U12.30(VA1.2_30) U12.50(VA1.2_50) VA1P2.1 Z4.3
VA1.8: C66.1 C67.1 C68.1 C69.1 C72.2 C73.2 C79.1 C80.1 C81.1 C82.1 C89.2 C90.2 C216.1 C217.1 U12.7(VA1.8_7) U12.15(VA1.8_15) U12.20(VA1.8_20) U12.29(VA1.8_29) U12.51(VA1.8_51) U12.56(VA1.8_56) VA1P8.1 Z7.3
VA3.0: C70.1 C71.1 C77.2 C78.2 C94.2 C95.2 C225.1 C226.1 R160.1 R164.1 U12.2(VA3.0_2) U12.13(VA3.0_13) U12.42(VA3.0_42) VA3.0.1 Z9.3
VA3.0_LED: C227.1 C228.1 JP1.1(PIN1) R57.2 R58.2 R68.1 U14.8(DIR4) VA3.0_LED.1 Z14.3
VADJ: FMC.E39 FMC.F40 FMC.G39 FMC.H40 R61.2 R69.1
VAMP: C24.2 C25.1 C26.2 C27.1 C241.1 C242.1 R30.2 R33.2 U3.14(+5V_14) U3.27(+5V_27) VAMP.1 Z17.3
VD1.2: C60.2 C61.1 C62.1 C86.2 C87.1 C88.1 C208.1 C209.1 U12.26(VD1.2_26) U12.45(VD1.2_45) VD1P2.1 Z6.3
VIO_B_M2C: FMC.J39 FMC.K40 R69.2
VLMK3.3: C134.1 C135.1 C191.2 C193.2 C235.1 C236.1 L20.2 L21.2 L24.1 L25.1 L26.1 L27.1 L28.1 LMK_RESET.1 LMK_SYNC.1 R17.1 U15.16(VCCA) U16.16(VCCA) VLMK3P3.1 Z11.3
VSPI1.8: C182.1 C184.1 C190.2 C192.2 C194.2 JP1.3(PIN3) JP2.1 R121.2 R122.2 R123.2 R124.2 U6.4(VCCIO) U14.15(VCCB) U15.15(VCCB) U16.15(VCCB) VSPI1.8.1 Z3.3
N17161280: C223.1 C224.1 R170.2 R179.1 U10.5(OUT) Z9.1 Z14.1
N17161345: C224.2 R170.1 R171.1 U10.6(ADJ)
